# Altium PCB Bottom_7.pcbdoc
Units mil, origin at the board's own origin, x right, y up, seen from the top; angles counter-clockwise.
Board outline 3200 x 3659.5 mil, 4 copper layers (Top Layer, Inner1, Inner2, Bottom Layer), stack 97.3 mil thick; 94 components, 190 nets, 554 pads, 104 vias.
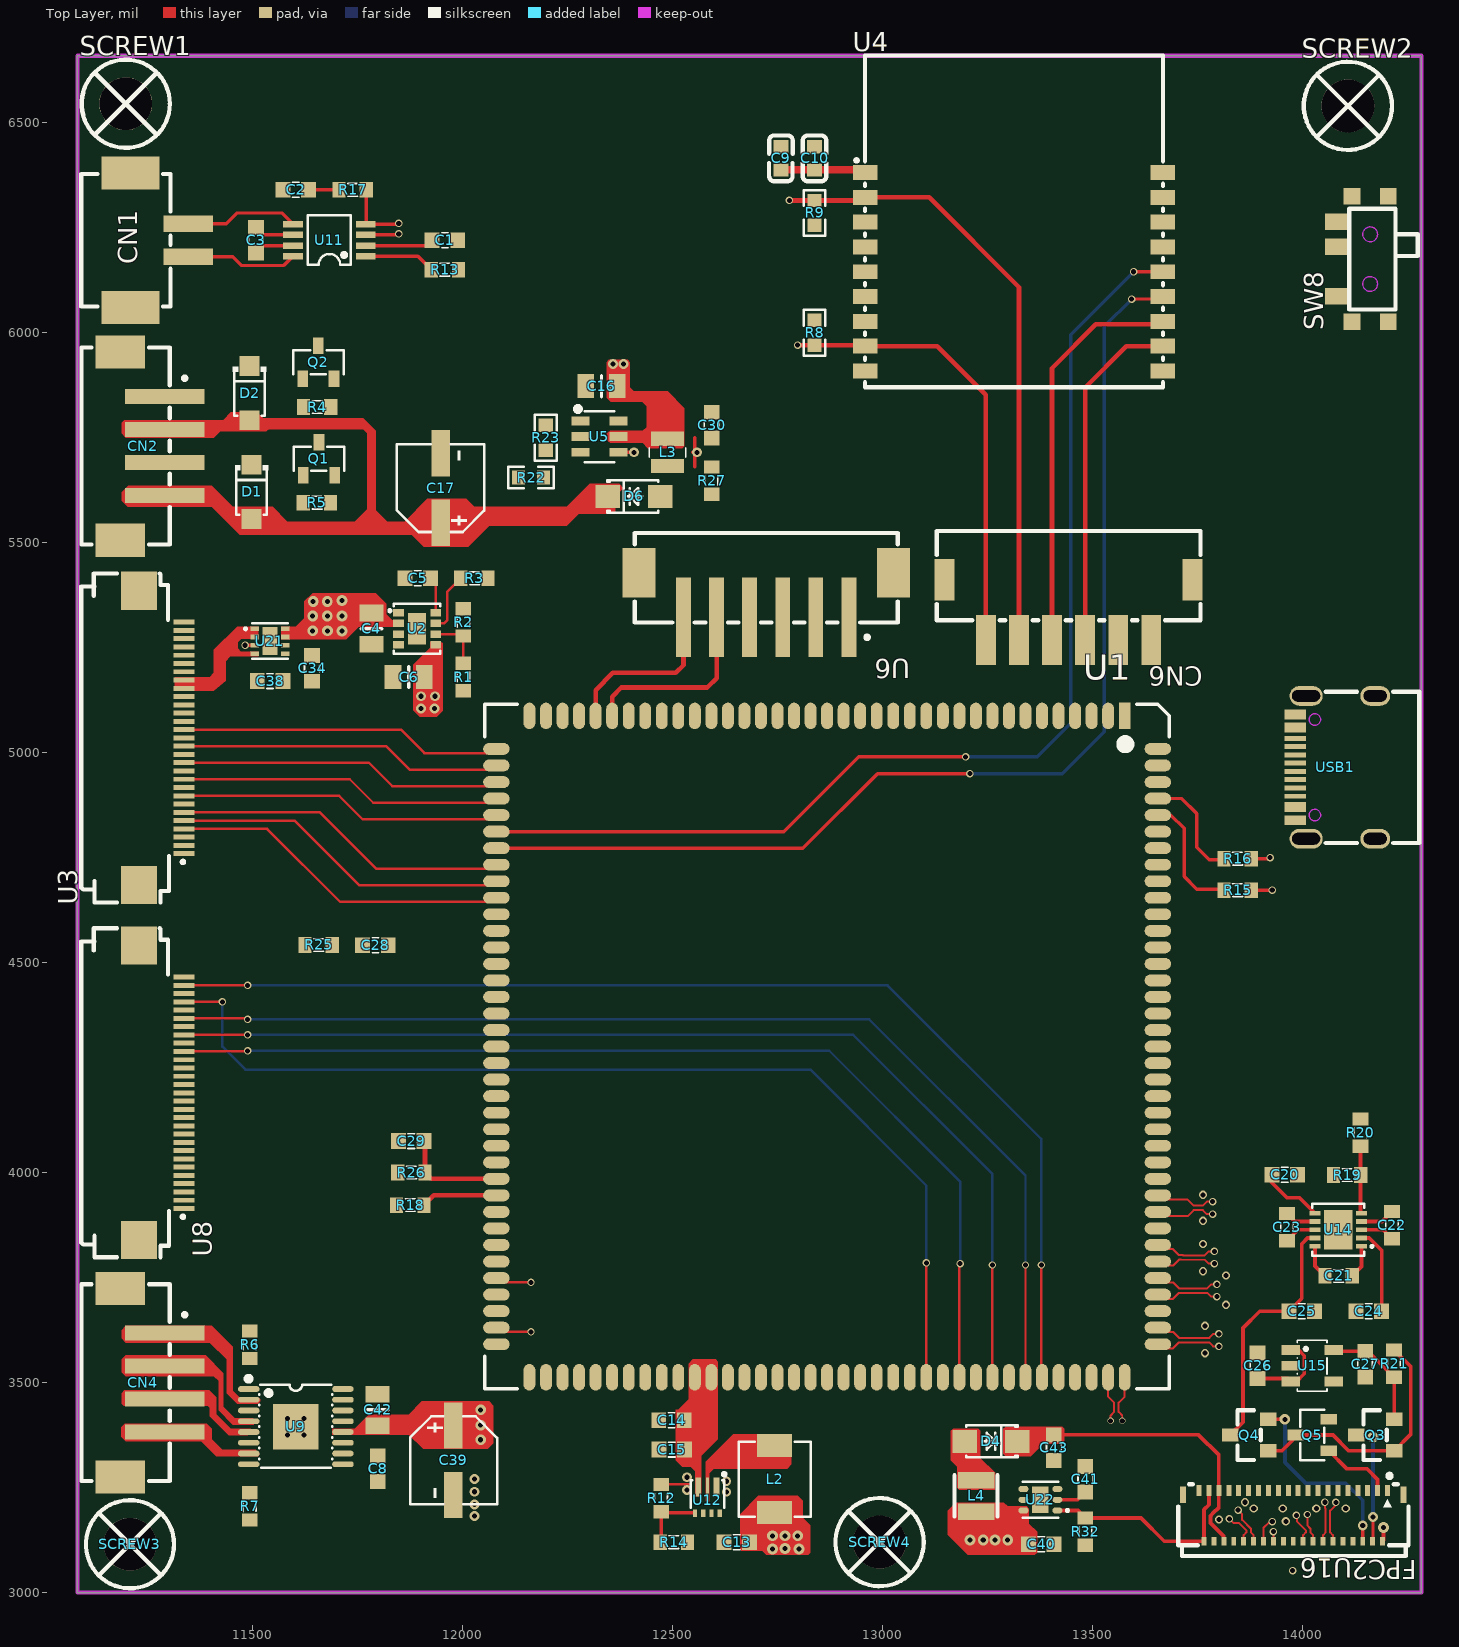
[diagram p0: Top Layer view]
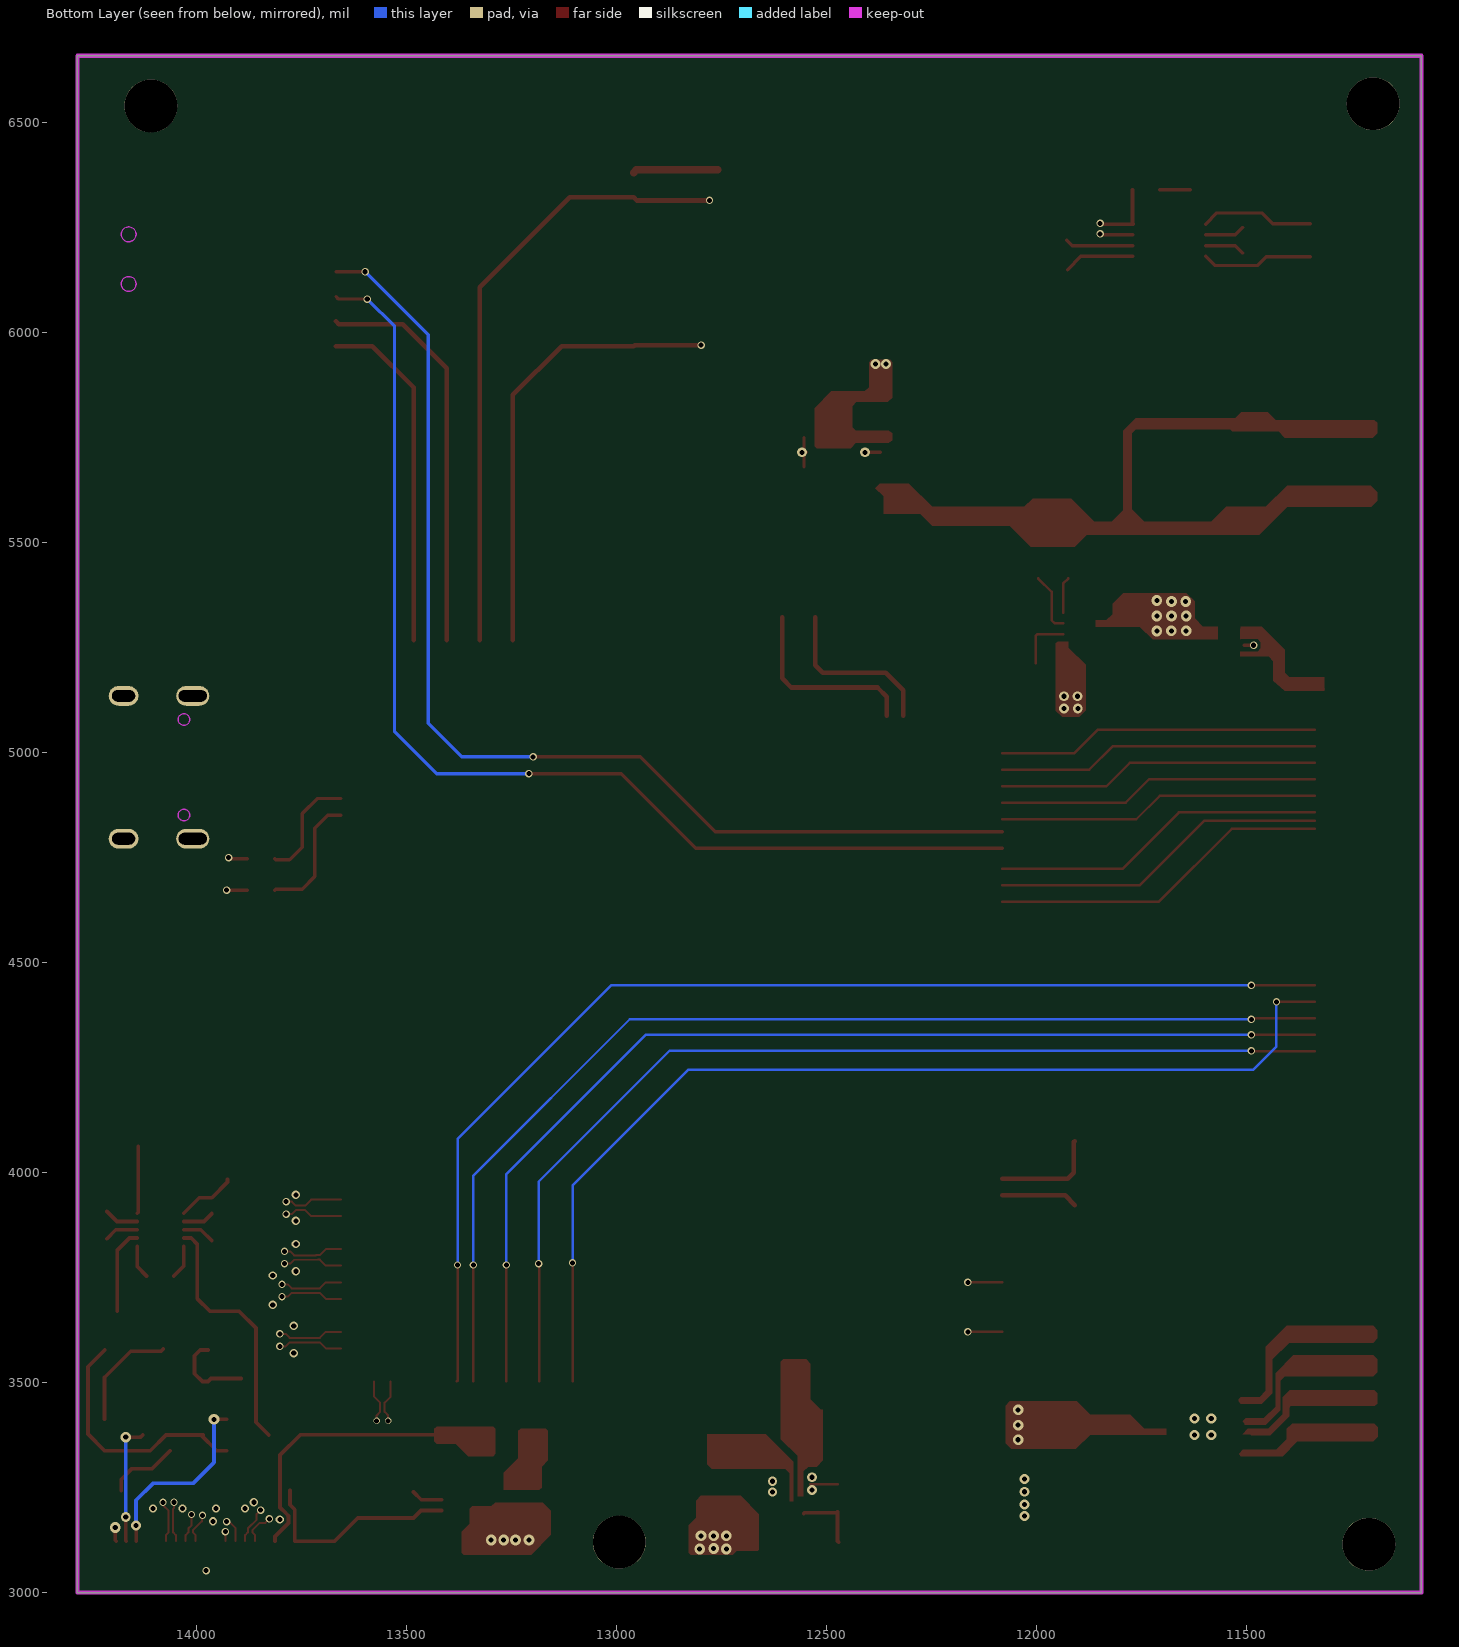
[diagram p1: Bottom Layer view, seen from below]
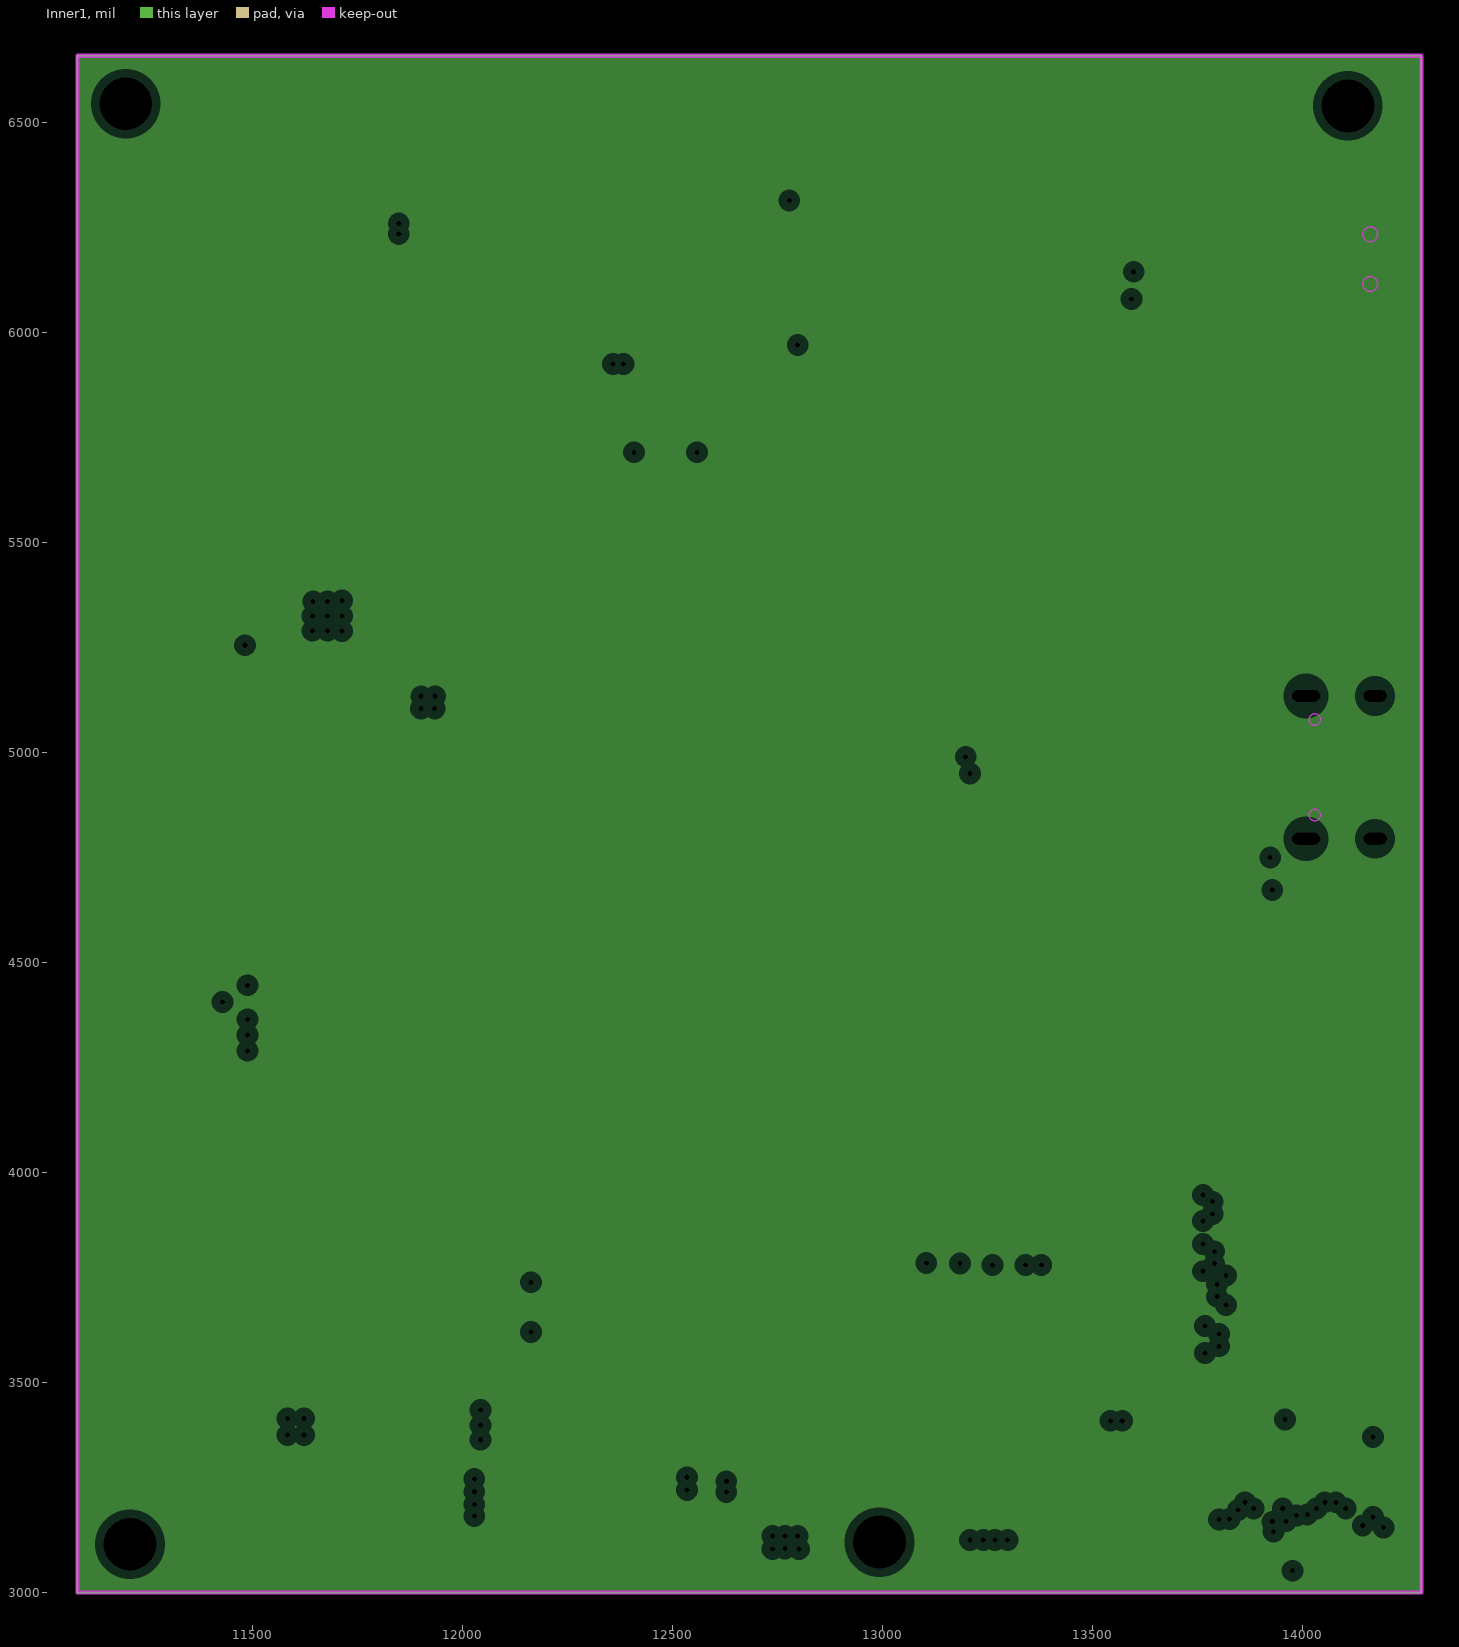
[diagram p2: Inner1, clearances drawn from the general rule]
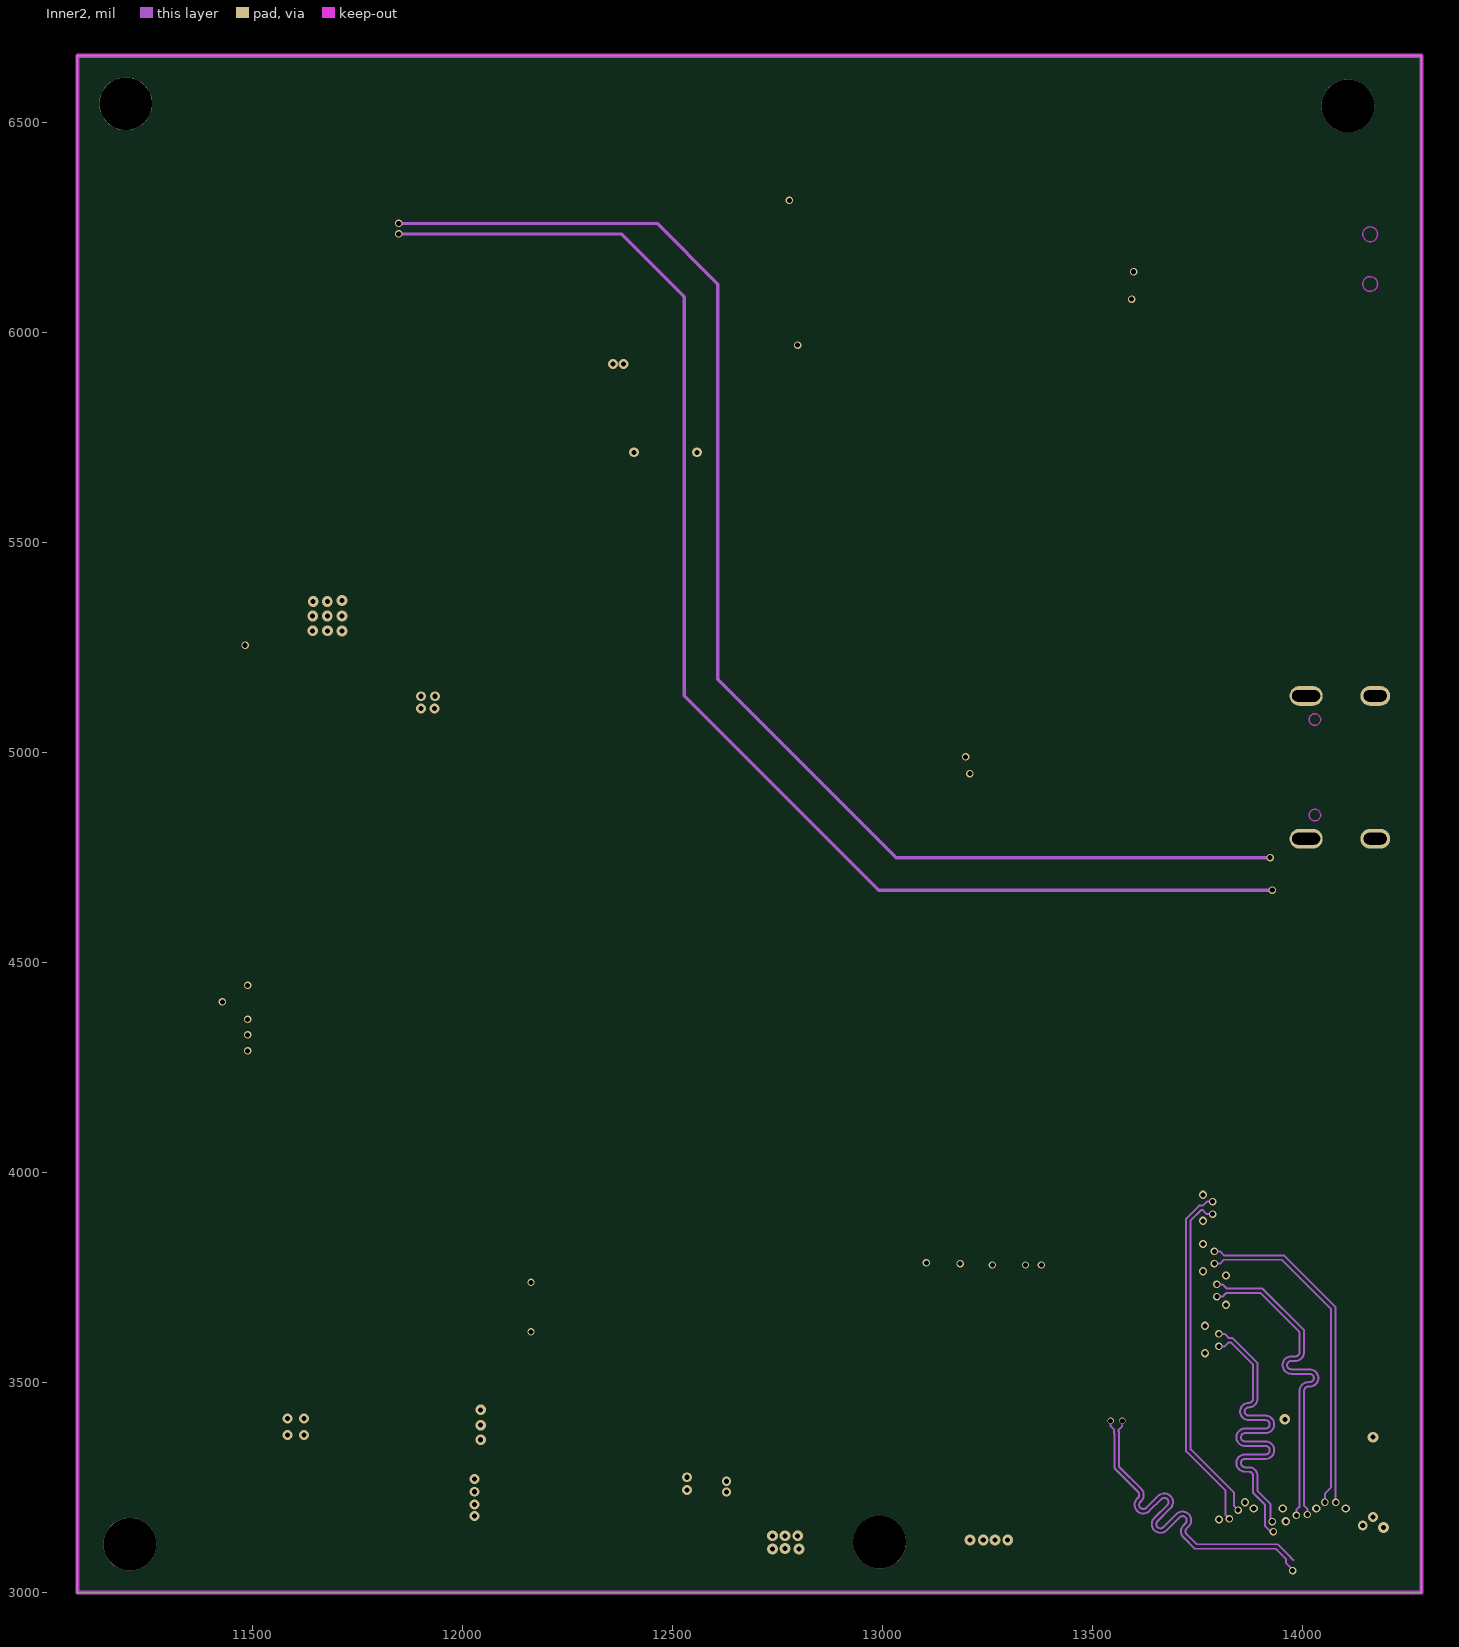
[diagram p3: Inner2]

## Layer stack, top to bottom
Top Solder Mask Layer: solder mask 0.4, Dk 3.3
Top Layer: signal copper 1.4
Inner1: plane copper (thickness not stored)
Inner2: signal copper (thickness not stored)
Dielectric5: surface 18.9, FR4, Dk 4.5
Dielectric6: surface 18.9, PP, Dk 4.5
Dielectric7: surface 18.9, PP, Dk 4.5
Dielectric8: surface 18.9, FR4, Dk 4.5
Dielectric9: surface 18.9, PP, Dk 4.5
Bottom Layer: signal copper 1.4
Bottom Solder Mask Layer: solder mask 0.4, Dk 3.3

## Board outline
11083,6659.5 14283,6659.5 14283,3000 11083,3000

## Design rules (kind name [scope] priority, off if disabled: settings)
BoardOutlineClearance copperThickness1oz [All] p0: genericclearance=10 ignorepadtopadclearanceinfootprint=FALSE except(0: Arc-SplitContinuation Track-SplitContinuation SMDPad-SplitContinuation THPad-SplitContinuation Via-SplitContinuation Fill-SplitContinuation Poly-SplitContinuation Region-SplitContinuation Text-SplitContinuation)
BoardOutlineClearance copperThickness2oz [All] p0: genericclearance=10 ignorepadtopadclearanceinfootprint=FALSE except(0: Arc-SplitContinuation Track-SplitContinuation SMDPad-SplitContinuation THPad-SplitContinuation Via-SplitContinuation Fill-SplitContinuation Poly-SplitContinuation Region-SplitContinuation Text-SplitContinuation)
BoardOutlineClearance copperThicknessInner0.5oz [All] p0: genericclearance=10 ignorepadtopadclearanceinfootprint=FALSE except(0: Arc-SplitContinuation Track-SplitContinuation SMDPad-SplitContinuation THPad-SplitContinuation Via-SplitContinuation Fill-SplitContinuation Poly-SplitContinuation Region-SplitContinuation Text-SplitContinuation)
BoardOutlineClearance 100ohm [All] p0: genericclearance=10 ignorepadtopadclearanceinfootprint=FALSE except(0: Arc-SplitContinuation Track-SplitContinuation SMDPad-SplitContinuation THPad-SplitContinuation Via-SplitContinuation Fill-SplitContinuation Poly-SplitContinuation Region-SplitContinuation Text-SplitContinuation)
BoardOutlineClearance otherClearance [All] p0: genericclearance=10 ignorepadtopadclearanceinfootprint=FALSE except(0: Arc-SplitContinuation Track-SplitContinuation SMDPad-SplitContinuation THPad-SplitContinuation Via-SplitContinuation Fill-SplitContinuation Poly-SplitContinuation Region-SplitContinuation Text-SplitContinuation)
Clearance copperThickness1oz [All] p1: gap=7 ignorepadtopadclearanceinfootprint=FALSE
Clearance copperThickness2oz [All] p1: gap=7 ignorepadtopadclearanceinfootprint=FALSE
Clearance copperThicknessInner0.5oz [All] p1: gap=7 ignorepadtopadclearanceinfootprint=FALSE
Clearance 100ohm [(InNet('DSI-D2P') OR InNet('DSI-D2N') OR InNet('DSI-D1P') OR InNet('DSI-D1N') OR InNet('DSI-CKP') OR InNet('DSI-CKN') OR InNet('DSI-D0P') OR InNet('DSI-D0N') OR InNet('DSI-D3P') OR InNet('DSI-D3N'))] p1: gap=7 ignorepadtopadclearanceinfootprint=FALSE
Clearance otherClearance [All] p1: gap=7 ignorepadtopadclearanceinfootprint=FALSE
DiffPairsRouting differentialPair [All] p1: maxuncoupledlength=10 minlimit=5.9843 maxlimit=Infinity mostfreqgap=5.9843 toplayer_minwidth=4 toplayer_prefwidth=10 toplayer_maxwidth=100 bottomlayer_minwidth=4 bottomlayer_prefwidth=10 bottomlayer_maxwidth=100 midlayer1_minwidth=4 midlayer1_prefwidth=10 midlayer1_maxwidth=100
PasteMaskExpansion pasteMaskExpansion [All] p1: expansion=0
PlaneConnect innerPlane [All] p1: planeconnectstyle=Relief reliefexpansion=20 reliefentries=4 reliefconductorwidth=10 reliefairgap=10
PolygonConnect copperRegion [All] p1: connectstyle=Relief reliefentries=4 reliefconductorwidth=10 polygonreliefangle="90 Angle" airgapwidth=10
RoutingVias viaSize [All] p1: viastyle="Through Hole" holewidth=12.0078 minholewidth=7.874 maxholewidth=248.0316 width=12.0078 minwidth=7.874 maxwidth=248.0316
SolderMaskExpansion solderMaskExpansion [IsVia] p1: useseparateexpansions=TRUE expansion=-1000 expansionbottom=-1000
SolderMaskExpansion solderMaskExpansion [All] p2: useseparateexpansions=TRUE expansion=2.0079 expansionbottom=2.0079
Width copperThickness1oz [All] p1: maxlimit=100 minlimit=4 preferedwidth=4
Width copperThickness2oz [All] p1: maxlimit=100 minlimit=8 preferedwidth=10
Width copperThickness0.5oz [All] p1: maxlimit=100 minlimit=4 preferedwidth=10
Width 100ohm [All] p1: maxlimit=100 minlimit=4 preferedwidth=5

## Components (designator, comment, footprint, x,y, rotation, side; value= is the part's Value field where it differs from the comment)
C1 "100nF" C0603#1 11958,6220 r0 top
C2 "100nF" C0603#1 11603,6340 r180 top
C3 "100nF" C0603#1 11508,6220 r90 top
C4 "100nF" C0603#2 11783,5295 r270 top
C5 "100nF" C0603#1 11893,5415 r0 top
C6 "100nF" C0603#2 11871.7,5180 r0 top
C8 "100nF" C0603#1 11798,3295 r90 top
C9 "100nF" C0603#3 12758,6415 r270 top
C10 "100nF" C0603#3 12838,6415 r270 top
C13 "100nF" C0603#1 12653,3120 r180 top
C14 "100nF" C0603#1 12497.5,3410 r180 top
C15 "100nF" C0603#1 12498,3340.5 r180 top
C16 "100nF" C0603#2 12330.6,5872.6 r0 top
C17 "100uF" CAP-SMD_BD5.0-L5.3-W5.3-LS6.0-FD-H5.7 11948,5630 r90 top
C20 "10uf" 0603_CAP#1 13958,3995 r180 top
C21 "2.2uf" 0603_CAP#2 14086,3754 r0 top
C22 "2.2uf" 0603_CAP#2 14213,3875 r90 top
C23 "2.2uf" 0603_CAP#2 13963,3870 r90 top
C24 "10uf" 0603_CAP#1 14158,3670 r0 top
C25 "10uf" 0603_CAP#1 13998,3670 r180 top
C26 "100nF" C0603#1 13893,3540 r270 top
C27 "100nF" C0603#1 14149.1,3543.9 r90 top
C28 "100nF" C0603#1 11792.6,4541.2 r180 top
C29 "100nF" C0603#1 11878,4075 r0 top
C30 "100nF" C0603#1 12593,5780 r270 top
C34 "100nF" C0603#4 11641.5,5200.3 r90 top
C38 "100nF" C0603#1 11541.5,5170.3 r180 top
C39 "100uF" CAP-SMD_BD5.0-L5.3-W5.3-LS6.0-FD-H5.7 11978,3315 r270 top
C40 "100nF" C0603#1 13378,3115 r180 top
C41 "100nF" C0603#1 13483,3270 r270 top
C42 "22uF" C0805 11798,3435 r270 top
C43 "100nF" C0603#1 13408,3345 r90 top
CN1 "PH2.0-2P-LT" CONN-SMD_PH2.0-1X2PW 11278,6220 r90 top
CN2 "2016WVS-04P" CONN-SMD_2016WVS-04P 11238,5730 r270 top
CN4 "2016WVS-04P" CONN-SMD_2016WVS-04P 11238,3500 r270 top
CN6 "XDWF-0221-06P" CONN-SMD_XDWF-0221-06P 13443,5340 r180 top
D1 "1N4007W" SOD-123FL_L2.7-W1.8-LS3.8-RD 11497.7,5620.9 r270 top
D2 "1N4007W" SOD-123FL_L2.7-W1.8-LS3.8-RD 11492.7,5855.9 r270 top
D4 "DSS16" SOD-123FL_L2.8-W1.8-LS3.7-R-RD 13258,3360 r180 top
D6 "DSS16" SOD-123FL_L2.8-W1.8-LS3.7-R-RD 12408,5610 r0 top
L2 "1uH" IND-SMD_L4.4-W4.2 12743,3270 r90 top
L3 "10uH" IND-SMD_L2.5-W2.0-VLS252012CX-150M 12488,5714.6 r270 top
L4 "10uH" IND-SMD_L2.5-W2.0_FHD252012S-6R8MT 13223,3230 r90 top
Q1 "AO3400A" SOT-23-3_L2.9-W1.3-P1.90-LS2.4-BR#1 11658,5700 r270 top
Q2 "AO3400A" SOT-23-3_L2.9-W1.3-P1.90-LS2.4-BR#2 11656.6,5929.5 r270 top
Q3 "AO3401A" SOT-23_L2.9-W1.3-P1.90-LS2.4-BR 14173,3375 r0 top
Q4 "AO3401A" SOT-23_L2.9-W1.3-P1.90-LS2.4-BR 13873,3375 r0 top
Q5 "AO3400A" SOT-23-3_L2.9-W1.3-P1.90-LS2.4-BR#1 14023,3375 r0 top
R1 "10K" R0603#1 12001.7,5180 r270 top
R2 "10K" R0603#1 12001.7,5310 r270 top
R3 "10K" R0603#1 12028,5415 r180 top
R4 "10K" R0603#2 11653.7,5822.8 r180 top
R5 "10K" R0603#1 11653,5595 r180 top
R6 "10K" R0603#1 11493,3590 r90 top
R7 "10K" R0603#1 11493,3205 r90 top
R8 "10K" R0603#3 12838,6000 r90 top
R9 "10K" R0603#3 12838,6285 r270 top
R12 "10K" R0603#1 12473,3225 r270 top
R13 "10K" R0603#1 11958,6150 r0 top
R14 "10K" R0603#1 12503,3120 r0 top
R15 "10K" R0603#1 13845.5,4672.5 r0 top
R16 "10K" R0603#1 13845.5,4747.5 r0 top
R17 "10K" R0603#1 11738,6340 r180 top
R18 "10K" R0603#1 11875.5,3922.5 r180 top
R19 "100K" 0603_RES 14106,3994 r180 top
R20 "10K" 0603_RES 14138,4095 r90 top
R21 "10K" R0603#1 14218,3545 r270 top
R22 "10K" R0603#3 12163,5655 r180 top
R23 "10K" R0603#3 12198,5750 r270 top
R25 "10K" R0603#1 11657.2,4541.9 r180 top
R26 "10K" R0603#1 11878,4000 r180 top
R27 "10K" R0603#1 12593,5647.8 r270 top
R32 "10K" R0603#1 13483,3145 r90 top
SCREW1 "" M3螺丝 11198,6545 r0 top
SCREW2 "" M3螺丝 14108,6540 r0 top
SCREW3 "" M3螺丝 11208,3115 r0 top
SCREW4 "" M3螺丝 12993,3120 r0 top
SW8 "SK-3296S-01-L1" SW-SMD_3P-P1.50_L2.7-W6.6 14143,6175 r90 top
U1 "CORE-T113-I" CORE-40X40-TAP148 12868,4300 r270 top
U2 "TPS82130SILR" USIP-8_L3.0-W2.8-P0.65-TL-EP 11891.7,5295 r0 top
U3 "AFD01-S29FCA-00" FPC-SMD_29P-P0.50_JS_AFD01-S29FCA-00 11283,5035 r90 top
U4 "2.4GHz" WIFI-SMD_L20.0-W18.0_ESP32-C3-WROOM-02U-N4 13313,6145 r0 top
U5 "MT3608" SOT-23-6_L2.9-W1.6-P0.95-LS2.8-BL 12325.8,5752.5 r270 top
U6 "2016WVS-06P" CONN-SMD_2016WVS-06P 12723,5375 r180 top
U8 "AFD01-S29FCA-00" FPC-SMD_29P-P0.50_JS_AFD01-S29FCA-00 11283,4190 r90 top
U9 "DRV8833PWPR" TSSOP-16_L5.0-W4.4-P0.65-LS6.4-BL-EP 11603,3395 r270 top
U11 "LM4890SS" MSOP-8_L3.0-W3.0-P0.65-LS4.9-BL-1 11683,6220 r90 top
U12 "TPS61022RWUT" VQFN-7_L2.0-W2.0-P0.55-TL_RWU 12583,3220 r270 top
U14 "LP3102QVF" TDFN-10_L3.0-W3.0-P0.50-BL-EP 14085.1,3863.8 r90 top
U15 "ME6211C18M5G-N" SOT-23-5_L3.0-W1.7-P0.95-LS2.8-BR 14023,3540 r180 top
U16 "FPC-0.3HF-39PWBH10" CONN-SMD_FPC-0.3HF-39PWBH10 13973,3180 r180 top locked
U21 "TPS22965DSGR" UDFN-8_L2.0-W2.0-P0.50-TL-EP 11541.5,5265.3 r0 top
U22 "TPS61165DRVR" WSON-6_L2.0-W2.0-P0.65-TL-EP 13376,3220.9 r180 top
USB1 "KH-TYPE-C-16P" USB-C-SMD_KH-TYPE-C-16P 14078,4965 r90 top

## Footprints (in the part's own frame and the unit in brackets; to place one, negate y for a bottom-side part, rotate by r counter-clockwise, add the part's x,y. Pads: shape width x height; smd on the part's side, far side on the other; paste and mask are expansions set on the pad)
0603_CAP#1 [mil]
  rect 35.4x37.4 smd: 1(-30.5,0) 2(30.5,0)
  silkscreen extent -8,-18 8,18
0603_CAP#2 [mil]
  rect 31.5x37.4 smd: 1(-32.5,0) 2(32.5,0)
  silkscreen extent -12,-15 12,15
0603_RES [mil]
  rect 31.5x37.4 smd: 1(-32.5,0) 2(32.5,0)
  silkscreen extent -12,-15 12,15
C0603#1 [mil]
  rect 35.4x37.4 smd: 1(-30.5,0) 2(30.5,0)
  silkscreen extent -8,-18 8,18
C0603#2 [mil]
  rect 39.4x57.1 smd: 1(-37.4,0) 2(37.4,0)
  silkscreen extent 0,-25 0,25
C0603#3 [mil]
  rect 31.5x35.4 smd: 1(-27.6,0) 2(27.6,0)
  silkscreen extent -55,-28 55,28
C0603#4 [mil]
  rect 35.4x37.4 smd: 1(-30.5,0) 2(30.6,0)
  silkscreen extent -8,-18 8,18
C0805 [mil]
  rect 39.4x57.1 smd: 1(-37.4,0) 2(37.4,0)
  silkscreen extent 0,-25 0,25
CAP-SMD_BD5.0-L5.3-W5.3-LS6.0-FD-H5.7 [mil]
  rect 110.2x43.3 smd: 1(-82.7,0) 2(82.7,0)
  silkscreen extent -105,-103 105,104
CONN-SMD_2016WVS-04P [mil]
  rect 35.4x189 smd: 1(-118.1,53.1) 2(-39.4,53.1) 3(39.4,53.1) 4(118.1,53.1)
  rect 78.7x118.1 smd: 5(224.4,-53.1) 6(-224.4,-53.1)
  silkscreen extent -234,-145 234,104
CONN-SMD_2016WVS-06P [mil]
  rect 35.4x189 smd: 1(-196.9,53.1) 2(-118.1,53.1) 3(-39.4,53.1) 4(39.4,53.1) 5(118.1,53.1) 6(196.9,53.1)
  rect 78.7x118.1 smd: 7(303.1,-53.1) 8(-303.1,-53.1)
  silkscreen extent -313,-148 313,104
CONN-SMD_FPC-0.3HF-39PWBH10 [mil]
  rect 11.8x26.4 smd paste+0 mask+2: 1(-229.4,-63) 3(-205.8,-63) 5(-182.2,-63) 7(-158.6,-63) 9(-134.9,-63) 11(-111.3,-63) 13(-87.7,-63) 15(-64.1,-63) 17(-40.4,-63) 19(-16.8,-63) 21(6.8,-63) 23(30.4,-63) 25(54,-63) 27(77.7,-63) 29(101.3,-63) 31(124.9,-63) 33(148.5,-63) 35(172.2,-63) 37(195.8,-63) 39(219.4,-63)
  rect 11.8x19.7 smd paste+0 mask+2: 2(-217.6,57.7) 4(-194,57.7) 6(-170.4,57.7) 8(-146.7,57.7) 10(-123.1,57.7) 12(-99.5,57.7) 14(-75.9,57.7) 16(-52.3,57.7) 18(-28.6,57.7) 20(-5,57.7) 22(18.6,57.7) 24(42.2,57.7) 26(65.9,57.7) 28(89.5,57.7) 30(113.1,57.7) 32(136.7,57.7) 34(160.3,57.7) 36(184,57.7) 38(207.6,57.7)
  rect 13.8x39.4 smd paste+0 mask+2: 40(257.8,-52.6) 41(-267.8,-52.6)
  silkscreen extent -279,-103 269,93
CONN-SMD_PH2.0-1X2PW [mil]
  rect 39.4x118.1 smd: 1(-39.4,-69.1) 2(39.4,-69.1)
  rect 78.7x137.8 smd: 3(160,69.1) 4(-160,69.1)
  silkscreen extent -158,-27 158,186
CONN-SMD_XDWF-0221-06P [mil]
  rect 47.2x118.1 smd: 1(-196.9,71.9) 2(-118.1,71.9) 3(-39.4,71.9) 4(39.4,71.9) 5(118.1,71.9) 6(196.8,71.9)
  rect 47.2x98.4 smd: 7(295.3,-71.9) 8(-295.3,-71.9)
  silkscreen extent -314,-188 314,25
CORE-40X40-TAP148 [mil]
  rect 63x28.3 smd: 1(-787.4,708.7)
  oval 63x28.3 smd: 2(-787.4,669.3) 3(-787.4,629.9) 4(-787.4,590.6) 5(-787.4,551.2) 6(-787.4,511.8) 7(-787.4,472.4) 8(-787.4,433.1) 9(-787.4,393.7) 10(-787.4,354.3) 11(-787.4,315) 12(-787.4,275.6) 13(-787.4,236.2) 14(-787.4,196.9) 15(-787.4,157.5) 16(-787.4,118.1) 17(-787.4,78.7) 18(-787.4,39.4) 19(-787.4,0) 20(-787.4,-39.4) 21(-787.4,-78.7) 22(-787.4,-118.1) 23(-787.4,-157.5) 24(-787.4,-196.9) 25(-787.4,-236.2) 26(-787.4,-275.6) 27(-787.4,-315) 28(-787.4,-354.3) 29(-787.4,-393.7) 30(-787.4,-433.1) 31(-787.4,-472.4) 32(-787.4,-511.8) 33(-787.4,-551.2) 34(-787.4,-590.6) 35(-787.4,-629.9) 36(-787.4,-669.3) 37(-787.4,-708.7) 75(787.4,-708.7) 76(787.4,-669.3) 77(787.4,-629.9) 78(787.4,-590.6) 79(787.4,-551.2) 80(787.4,-511.8) 81(787.4,-472.4) 82(787.4,-433.1) 83(787.4,-393.7) 84(787.4,-354.3) 85(787.4,-315) 86(787.4,-275.6) 87(787.4,-236.2) 88(787.4,-196.9) 89(787.4,-157.5) 90(787.4,-118.1) 91(787.4,-78.7) 92(787.4,-39.4) 93(787.4,0) 94(787.4,39.4) 95(787.4,78.7) 96(787.4,118.1) 97(787.4,157.5) 98(787.4,196.9) 99(787.4,236.2) 100(787.4,275.6) 101(787.4,315) 102(787.4,354.3) 103(787.4,393.7) 104(787.4,433.1) 105(787.4,472.4) 106(787.4,511.8) 107(787.4,551.2) 108(787.4,590.6) 109(787.4,629.9) 110(787.4,669.3) 111(787.4,708.7)
  oval 28.3x63 smd: 38(-708.7,-787.4) 39(-669.3,-787.4) 40(-629.9,-787.4) 41(-590.6,-787.4) 42(-551.2,-787.4) 43(-511.8,-787.4) 44(-472.4,-787.4) 45(-433.1,-787.4) 46(-393.7,-787.4) 47(-354.3,-787.4) 48(-315,-787.4) 49(-275.6,-787.4) 50(-236.2,-787.4) 51(-196.8,-787.4) 52(-157.5,-787.4) 53(-118.1,-787.4) 54(-78.7,-787.4) 55(-39.4,-787.4) 56(0,-787.4) 57(39.4,-787.4) 58(78.7,-787.4) 59(118.1,-787.4) 60(157.5,-787.4) 61(196.9,-787.4) 62(236.2,-787.4) 63(275.6,-787.4) 64(315,-787.4) 65(354.3,-787.4) 66(393.7,-787.4) 67(433.1,-787.4) 68(472.4,-787.4) 69(511.8,-787.4) 70(551.2,-787.4) 71(590.6,-787.4) 72(629.9,-787.4) 73(669.3,-787.4) 74(708.7,-787.4) 112(708.7,787.4) 113(669.3,787.4) 114(629.9,787.4) 115(590.6,787.4) 116(551.2,787.4) 117(511.8,787.4) 118(472.4,787.4) 119(433.1,787.4) 120(393.7,787.4) 121(354.3,787.4) 122(315,787.4) 123(275.6,787.4) 124(236.2,787.4) 125(196.9,787.4) 126(157.5,787.4) 127(118.1,787.4) 128(78.7,787.4) 129(39.4,787.4) 130(0,787.4) 131(-39.4,787.4) 132(-78.7,787.4) 133(-118.1,787.4) 134(-157.5,787.4) 135(-196.8,787.4) 136(-236.2,787.4) 137(-275.6,787.4) 138(-315,787.4) 139(-354.3,787.4) 140(-393.7,787.4) 141(-433.1,787.4) 142(-472.4,787.4) 143(-511.8,787.4) 144(-551.2,787.4) 145(-590.6,787.4) 146(-629.9,787.4) 147(-669.3,787.4) 148(-708.7,787.4)
  silkscreen extent -815,-815 815,815
FPC-SMD_29P-P0.50_JS_AFD01-S29FCA-00 [mil]
  rect 11.8x49.2 smd paste+0 mask+2: 1(-275.6,-53.6) 2(-255.9,-53.6) 3(-236.2,-53.6) 4(-216.5,-53.6) 5(-196.8,-53.6) 6(-177.2,-53.6) 7(-157.5,-53.6) 8(-137.8,-53.6) 9(-118.1,-53.6) 10(-98.4,-53.6) 11(-78.7,-53.6) 12(-59.1,-53.6) 13(-39.4,-53.6) 14(-19.7,-53.6) 15(0,-53.6) 16(19.7,-53.6) 17(39.4,-53.6) 18(59,-53.6) 19(78.7,-53.6) 20(98.4,-53.6) 21(118.1,-53.6) 22(137.8,-53.6) 23(157.5,-53.6) 24(177.2,-53.6) 25(196.8,-53.6) 26(216.5,-53.6) 27(236.2,-53.6) 28(255.9,-53.6) 29(275.6,-53.6)
  rect 90.6x86.6 smd paste+0 mask+2: 30(350.4,53.6) 31(-350.4,53.6)
  silkscreen extent -392,-55 392,191
IND-SMD_L2.5-W2.0-VLS252012CX-150M [mil]
  rect 33.5x78.7 smd: 1(-32.7,0) 2(32.6,0)
  silkscreen extent -11,-43 11,43
IND-SMD_L2.5-W2.0_FHD252012S-6R8MT [mil]
  rect 39.4x86.6 smd: 1(-37.4,0) 2(37.4,0)
  silkscreen extent -49,-51 49,52
IND-SMD_L4.4-W4.2 [mil]
  rect 55.1x83.5 smd: 1(79.8,0) 2(-79.8,0)
  silkscreen extent -90,-86 90,86
M3螺丝 [mil]
  round 126 hole 126 paste+0 mask+4: 1(0,0)
  silkscreen extent -105,-105 105,105
MSOP-8_L3.0-W3.0-P0.65-LS4.9-BL-1 [mil]
  rect 16x47.2 smd: 1(-38.4,-86.6) 2(-12.8,-86.6) 3(12.8,-86.6) 4(38.4,-86.6) 5(38.4,86.6) 6(12.8,86.6) 7(-12.8,86.6) 8(-38.4,86.6)
  silkscreen extent -58,-51 59,51
R0603#1 [mil]
  rect 31.5x37.4 smd: 1(-32.5,0) 2(32.5,0)
  silkscreen extent -12,-15 12,15
R0603#2 [mil]
  rect 31.5x37.4 smd: 1(-32.5,0) 2(32.4,0)
  silkscreen extent -12,-15 12,15
R0603#3 [mil]
  rect 31.8x34 smd paste-3937 mask+2: 1(-29.7,0) 2(29.7,0)
  silkscreen extent -54,-26 54,26
SOD-123FL_L2.7-W1.8-LS3.8-RD [mil]
  rect 47.2x47.2 smd: 1(-64.4,0) 2(64.4,0)
  silkscreen extent -63,-40 54,39
SOD-123FL_L2.8-W1.8-LS3.7-R-RD [mil]
  rect 58.3x55.1 smd paste+0 mask+2: 1(62.6,0) 2(-62.6,0)
  silkscreen extent -64,-38 58,38
SOT-23-3_L2.9-W1.3-P1.90-LS2.4-BR#1 [mil]
  rect 39.4x25.6 smd: 1(39.4,-37.4) 2(39.4,37.4) 3(-39.4,0)
  silkscreen extent -29,-60 29,60
SOT-23-3_L2.9-W1.3-P1.90-LS2.4-BR#2 [mil]
  rect 39.4x25.6 smd: 1(39.4,-37.4) 2(39.4,37.4) 3(-39.3,0)
  silkscreen extent -29,-60 29,60
SOT-23-5_L3.0-W1.7-P0.95-LS2.8-BR [mil]
  rect 43.3x23.6 smd: 1(51.2,-37.4) 2(51.2,0) 3(51.2,37.4) 4(-51.2,37.4) 5(-51.2,-37.4)
  silkscreen extent -35,-61 35,61
SOT-23-6_L2.9-W1.6-P0.95-LS2.8-BL [mil]
  rect 20.9x42.2 smd: 1(-37.4,-45.2) 2(0,-45.2) 3(37.4,-45.2) 4(37.4,45.3) 5(0,45.3) 6(-37.4,45.3)
  silkscreen extent -72,-57 61,35
SOT-23_L2.9-W1.3-P1.90-LS2.4-BR [mil]
  rect 39.4x31.5 smd: 1(45.3,-37.4) 2(45.3,37.4) 3(-45.3,0)
  silkscreen extent -28,-59 28,59
SW-SMD_3P-P1.50_L2.7-W6.6 [mil]
  rect 39.4x39.4 smd: 0(-149.6,-61.4) 0(-149.6,25.2) 0(149.6,-61.4) 0(149.6,25.2)
  rect 39.4x55.1 smd: 1(-88.6,61.4) 2(29.5,61.4) 3(88.6,61.4)
  Board Outline Layer circle w0.1: c-59.1,-18.1 r17.7
  Board Outline Layer circle w0.1: c59.1,-18.1 r17.7
  Board Outline Layer region: -59.1,-35.8 -66.78,-34.05 -72.94,-29.14 -76.36,-22.04 -76.36,-14.16 -72.94,-7.06 -66.78,-2.15 -59.1,-0.4 -59.1,-0.4 -51.42,-2.15 -45.26,-7.06 -41.84,-14.16 -41.84,-22.04 -45.26,-29.14 -51.42,-34.05 -59.1,-35.8
  Board Outline Layer region: -59.1,-35.8 -66.78,-34.05 -72.94,-29.14 -76.36,-22.04 -76.36,-14.16 -72.94,-7.06 -66.78,-2.15 -59.1,-0.4 -59.1,-0.4 -51.42,-2.15 -45.26,-7.06 -41.84,-14.16 -41.84,-22.04 -45.26,-29.14 -51.42,-34.05 -59.1,-35.8
  Board Outline Layer region: 59.1,-35.8 51.42,-34.05 45.26,-29.14 41.84,-22.04 41.84,-14.16 45.26,-7.06 51.42,-2.15 59.1,-0.4 59.1,-0.4 66.78,-2.15 72.94,-7.06 76.36,-14.16 76.36,-22.04 72.94,-29.14 66.78,-34.05 59.1,-35.8
  Board Outline Layer region: 59.1,-35.8 51.42,-34.05 45.26,-29.14 41.84,-22.04 41.84,-14.16 45.26,-7.06 51.42,-2.15 59.1,-0.4 59.1,-0.4 66.78,-2.15 72.94,-7.06 76.36,-14.16 76.36,-22.04 72.94,-29.14 66.78,-34.05 59.1,-35.8
  silkscreen extent -120,-131 120,32
TDFN-10_L3.0-W3.0-P0.50-BL-EP [mil]
  rect 11x26.2 smd: 1(-39.4,-55.4) 2(-19.7,-55.4) 3(0,-55.4) 4(19.7,-55.4) 5(39.4,-55.4) 6(39.4,55.4) 7(19.7,55.4) 8(0,55.4) 9(-19.7,55.4) 10(-39.4,55.4)
  rect 94.5x66.9 smd: 11(0,0)
  silkscreen extent -62,-83 62,62
TSSOP-16_L5.0-W4.4-P0.65-LS6.4-BL-EP [mil]
  oval 13.8x51.2 smd: 1(-89.6,-112.2) 2(-64,-112.2) 3(-38.4,-112.2) 4(-12.8,-112.2) 5(12.8,-112.2) 6(38.4,-112.2) 7(64,-112.2) 8(89.6,-112.2) 9(89.6,112.2) 10(64,112.2) 11(38.4,112.2) 12(12.8,112.2) 13(-12.8,112.2) 14(-38.4,112.2) 15(-64,112.2) 16(-89.6,112.2)
  rect 107.9x107.9 smd: 17(0,0)
  silkscreen extent -120,-118 98,87
UDFN-8_L2.0-W2.0-P0.50-TL-EP [mil]
  rect 19.9x11 smd: 1(-36.6,29.6) 2(-36.6,9.9) 3(-36.6,-9.8) 4(-36.6,-29.5) 5(36.5,-29.5) 6(36.5,-9.8) 7(36.5,9.9) 8(36.5,29.6)
  rect 35.4x66.9 smd: 9(0,0)
  silkscreen extent -61,-42 42,42
USB-C-SMD_KH-TYPE-C-16P [mil]
  oval 47.2x78.7 hole 27.6 slot 66.9 at 90 deg paste+0 mask+2: 1(-170.1,69.5) 2(170.1,69.5)
  oval 47.2x70.9 hole 27.6 slot 55.1 at 90 deg paste+0 mask+2: 3(-170.1,-95.1) 4(170.1,-95.1)
  rect 11.8x51.2 smd paste-3937 mask+2: A1(-131.9,95.1) A4(-100.4,95.1) A5(-49.2,95.1) A6(-9.8,95.1) A7(9.8,95.1) A8(49.2,95.1) A9(100.4,95.1) A12(131.9,95.1) B1(120.1,95.1) B4(88.6,95.1) B5(68.9,95.1) B6(29.5,95.1) B7(-29.5,95.1) B8(-68.9,95.1) B9(-88.6,95.1) B12(-120.1,95.1)
  Board Outline Layer circle w0.1: c-113.8,48.6 r13.8
  Board Outline Layer circle w0.1: c113.8,48.6 r13.8
  Board Outline Layer region: -113.8,34.8 -119.79,36.17 -124.59,40 -127.25,45.53 -127.25,51.67 -124.59,57.2 -119.79,61.03 -113.8,62.4 -113.8,62.4 -107.81,61.03 -103.01,57.2 -100.35,51.67 -100.35,45.53 -103.01,40 -107.81,36.17 -113.8,34.8
  Board Outline Layer region: -113.8,34.8 -119.79,36.17 -124.59,40 -127.25,45.53 -127.25,51.67 -124.59,57.2 -119.79,61.03 -113.8,62.4 -113.8,62.4 -107.81,61.03 -103.01,57.2 -100.35,51.67 -100.35,45.53 -103.01,40 -107.81,36.17 -113.8,34.8
  Board Outline Layer region: 113.8,34.8 107.81,36.17 103.01,40 100.35,45.53 100.35,51.67 103.01,57.2 107.81,61.03 113.8,62.4 113.8,62.4 119.79,61.03 124.59,57.2 127.25,51.67 127.25,45.53 124.59,40 119.79,36.17 113.8,34.8
  Board Outline Layer region: 113.8,34.8 107.81,36.17 103.01,40 100.35,45.53 100.35,51.67 103.01,57.2 107.81,61.03 113.8,62.4 113.8,62.4 119.79,61.03 124.59,57.2 127.25,51.67 127.25,45.53 124.59,40 119.79,36.17 113.8,34.8
  silkscreen extent -180,-200 180,23
USIP-8_L3.0-W2.8-P0.65-TL-EP [mil]
  rect 25.6x17.7 smd: 1(-44.3,38.4) 2(-44.3,12.8) 3(-44.3,-12.8) 4(-44.3,-38.4) 5(44.3,-38.4) 6(44.3,-12.8) 7(44.3,12.8) 8(44.3,38.4)
  rect 43.3x74.8 smd: 9(0,0)
  silkscreen extent -68,-59 55,59
VQFN-7_L2.0-W2.0-P0.55-TL_RWU [mil]
  rect 45.3x13.8 smd paste+0 mask+2: 1(-31.5,21.6) 3(-31.5,-21.7)
  rect 57.1x7.9 smd paste+0 mask+2: 2(-25.6,0)
  rect 17.7x9.8 smd paste+0 mask+2: 4(31.5,-29.5) 5(31.5,-9.8) 6(31.5,9.8) 7(31.5,29.5)
  silkscreen extent -66,-40 18,44
WIFI-SMD_L20.0-W18.0_ESP32-C3-WROOM-02U-N4 [mil]
  rect 59.1x35.4 smd paste+0 mask+2: 1(-354.3,236.2) 2(-354.3,177.2) 3(-354.3,118.1) 4(-354.3,59.1) 5(-354.3,0) 6(-354.3,-59.1) 7(-354.3,-118.1) 8(-354.3,-177.2) 9(-354.3,-236.2) 10(354.3,-236.2) 11(354.3,-177.2) 12(354.3,-118.1) 13(354.3,-59.1) 14(354.3,0) 15(354.3,59.1) 16(354.3,118.1) 17(354.3,177.2) 18(354.3,236.2)
  silkscreen extent -379,-275 355,515
WSON-6_L2.0-W2.0-P0.65-TL-EP [mil]
  oval 23.9x14.3 smd: 1(-40.4,25.6) 2(-40.4,0) 3(-40.4,-25.6) 4(40.5,-25.6) 5(40.5,0) 6(40.5,25.6)
  rect 39.4x63 smd: 7(0,0)
  silkscreen extent -67,-42 42,42

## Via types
v1: diameter 17.7, hole 12, Top Layer to Bottom Layer, 40 vias
v2: diameter 25.6, hole 12, Top Layer to Bottom Layer, 25 vias
v3: diameter 23.6, hole 12, Top Layer to Bottom Layer, 16 vias
v4: diameter 19.7, hole 12, Top Layer to Bottom Layer, 15 vias
v5: diameter 24, hole 12, Top Layer to Bottom Layer, 4 vias
v6: diameter 15.7, hole 12, Top Layer to Bottom Layer, 2 vias
v7: diameter 21.7, hole 12, Top Layer to Bottom Layer, 2 vias

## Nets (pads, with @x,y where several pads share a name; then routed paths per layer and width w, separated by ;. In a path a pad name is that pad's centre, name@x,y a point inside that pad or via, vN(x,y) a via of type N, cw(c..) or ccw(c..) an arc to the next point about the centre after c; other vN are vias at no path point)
1ADC_RDY: U1.38 U3.16 | length 767.2
  Top Layer w5.9: U3.16 11853.3,5054.7 11909.3,4998.7 U1.38@12080.6,4998.7
1SCLK: U1.42 U3.8 | length 767.2
  Top Layer w5.9: U3.8 11705.8,4897.2 11761.8,4841.2 U1.42@12080.6,4841.2
1SPISIMO: U1.40 U3.12 | length 767.2
  Top Layer w5.9: U3.12 11777.1,4975.9 11833.1,4919.9 U1.40@12080.6,4919.9
1SPISOMI: U1.41 U3.10 | length 767.2
  Top Layer w5.9: U3.10 11731.4,4936.6 11787.4,4880.6 U1.41@12080.6,4880.6
1SPISTE: U1.39 U3.14 | length 767.2
  Top Layer w5.9: U3.14 11817.7,5015.3 11873.7,4959.3 U1.39@12080.6,4959.3
3V3: U3.1 U3.2
3V3_AFE: C28.2 R25.1 U2.1
5V: C14.1 C15.1 C39.1 C40.2 C42.2 L4.1 R12.1 U1.85 U1.86 U1.87 U9.12 U12.3 U22.6 | length 65
  Top Layer w5.9: R12.1 12538,3257.5
  other v2: 13208,3125 13239.8,3125 13268,3125 13298,3125 12043,3363.8 12043,3398.4 12043,3435
  other v3: 12534.4,3244.1 12534.4,3274.5
12V: C17.1 CN2.2 CN2.4 D1.2 D2.2 D6.2 R22.2
$25N41: C5.2 U2.8 | length 86.8
  Top Layer w5.9: C5.2 11936,5402.5 U2.8
$25N130: R1.1 R2.2 U2.6 | length 132.6
  Top Layer w5.9: U2.6 11997,5282.2 R2.2 R1.1
$25N148: CN4.1 U9.2
$25N149: CN4.2 U9.4
$25N150: CN4.3 U9.5
$25N151: CN4.4 U9.7
$25N152: CN2.1 D2.1 Q2.3
$25N153: CN2.3 D1.1 Q1.3
$25N161: C8.2 U9.11
$25N181: L2.1 U12.2
$25N184: R12.2 R14.1 U12.4 | length 155.7
  Top Layer w9: R14.1 12473,3122.5 R12.2 12475.5,3190 12552,3190 U12.4
$25N191: Q4.2 U16.6 | length 452.2
  Top Layer w8: U16.6 v3(14143.4,3160)
  Top Layer w9: Q4.2@13928.3,3412.4 v2(13958,3412.4)
  Bottom Layer w9: v2(13958,3412.4) 13958,3310 14008,3260 14103,3260 14143.4,3219.6 v3(14143.4,3160)
$25N194: Q3.1 Q4.1 Q5.3 R21.1 | length 598.9
  Top Layer w9: Q4.1@13928.3,3337.6 13951.2,3337.6 Q5.3@13988.6,3375 ; Q5.3 Q5.3@13988.6,3375 ; R21.1 14258,3537.5 14258,3377.3 Q3.1 14109.7,3337.6 14072.3,3375 Q5.3@13988.6,3375
$25N195: Q3.3 U16.4 | length 290.5
  Top Layer w8: U16.4 14168,3123.4 14168,3145 v3(14168,3180)
  Top Layer w9: Q3.3 14132.7,3370 v2(14168,3370)
  Bottom Layer w9: v3(14168,3180) v2(14168,3370)
$25N207: R19.1 R20.1 U14.5 | length 160.3
  Top Layer w9: R20.1 14138,3905.7 U14.5
$25N212: C23.2 U14.7 | length 74.6
  Top Layer w9: C23.2 13982,3883.5 U14.7
$25N213: C23.1 U14.8 | length 77.6
  Top Layer w9: C23.1 13989.3,3863.8 U14.8
$25N214: C21.2 U14.1 | length 79.5
  Top Layer w9: C21.2 14140.5,3776.1 U14.1
$25N215: C22.2 U14.4 | length 82.4
  Top Layer w9: U14.4 14189,3883.5 C22.2
$25N216: C22.1 U14.3 | length 81.3
  Top Layer w9: U14.3 14191.7,3863.8 C22.1
$25N217: C21.1 U14.10 | length 80.3
  Top Layer w9: U14.10 14029.7,3777.8 C21.1
$25N282: C34.2 U21.6
$25N291: SW8.3 U21.3 | length 22.7
  Top Layer w8: v1(11482.3,5255.6) 11504.9,5255.6 U21.3
$25N348: C41.2 U22.2 | length 74.3
  Top Layer w9: U22.2 13464.4,3220.9 C41.2
$25N352: D4.1 L4.2 U22.4
$25N531: R22.1 R23.2 U5.3
$25N536: CN6.6 R8.1 U4.8 | length 1081
  Top Layer w11: v1(12798,5970.3) R8.1 12956.2,5970.3 U4.8 13130.2,5967.8 13246.2,5851.8 CN6.6
$25N537: C9.2 C10.2 CN6.1 U4.1 | length 203.2
  Top Layer w18: C9.2 C10.2 12952.4,6387.4 U4.1
$25N539: CN6.5 R9.1 U4.2 | length 1478.8
  Top Layer w11: v1(12778,6315) 12778.3,6314.7 R9.1 12951.2,6314.7 U4.2 13110.8,6322.2 13324.9,6108.1 CN6.5
$25N544: CN6.4 U4.12 | length 957.3
  Top Layer w11: CN6.4 13403.6,5915.6 13508,6020 13660.4,6020 U4.12
$25N545: CN6.3 U4.11 | length 827
  Top Layer w11: CN6.3 13482.4,5869.4 13580.8,5967.8 U4.11
$25N598: D6.1 L3.2 U5.1
$28N1: U1.91
$28N2: U1.90
$28N45: U1.54
$28N46: U1.55
$28N47: U1.56
$28N48: U1.57
$28N49: U1.58
$28N72: U1.50
$28N135: U1.146
$28N136: U1.147
$28N153: R16.2 R17.1 U11.4 | length 3458.2
  Top Layer w8: U11.4 11846.4,6258.4 v1(11848,6260) ; R16.2 13920.5,4747.5 v1(13923,4750)
  Top Layer w9: U11.4 11770.5,6259.3 R17.1
  Inner2 w8: v1(11848,6260) 12463,6260 12608,6115 12608,5175 13033,4750 v1(13923,4750)
$28N155: R13.1 U11.1 | length 169
  Top Layer w8: U11.1 11893.9,6181.6 R13.1
$28N157: C1.1 U11.2 | length 163.2
  Top Layer w8: U11.2 11914.7,6207.2 C1.1
$28N159: C2.1 R17.2 | length 72
  Top Layer w9: C2.1 R17.2
$28N163: CN1.2 U11.5 | length 270.9
  Top Layer w8: CN1.2 11437.4,6259.4 11463,6285 11569.8,6285 U11.5
$28N164: CN1.1 U11.8 | length 266.8
  Top Layer w8: CN1.1 11452.4,6180.6 11473,6160 11574.8,6160 U11.8
$28N197: R15.2 U11.3 | length 3413
  Top Layer w8: U11.3 11845.8,6232.8 v1(11848,6235) ; R15.2 v1(13928,4672.5)
  Inner2 w8: v1(11848,6235) 12378,6235 12528,6085 12528,5135 12990.5,4672.5 v1(13928,4672.5)
+VPS: C3.2 C4.1 C13.1 C16.2 L2.2 L3.1 R13.2 R25.2 R27.2 U2.2 U5.5 U8.11 U8.12 U11.6 U12.5 U12.7 U21.7 U21.8 | length 95.7
  Top Layer w8: C3.2 11525.7,6232.8 U11.6
  other v2: 12738,3103.8 12801.3,3103.8 12768,3105 12738,3135 12768,3135 12798,3135 11643,5290 11678.3,5290 11713,5289.8 11643,5325 11678,5325 11713,5325 11644.3,5360 11678,5360 11713,5362.4
  other v3: 12358,5925 12383,5925
A: U1.34
A1: U1.94 U9.16
A2: U1.95 U9.15
A11/TP_X2: U1.21
A17/MIC_DET: U1.6
A18/FEL/3V3: R18.1 U1.65 U6.4 | length 182.2
  Top Layer w11: R18.1 11931.2,3945.7 U1.65
ACS: U1.122
ADRDY: U1.127
AGND: U3.3 U3.7 U3.9 U3.11 U3.13 U3.15 U3.17 U3.20 U3.23 U3.29 U8.13 U8.14 U8.19 U8.21 U8.23 U8.25 U8.27 U8.29
ASCLK: U1.123
ASCO: U1.126
ASDI: U1.125
B: U1.35
B1: U1.97 U9.9
B2: U1.96 U9.10
B9/TVIN0: U1.17
B11/TP_Y1: U1.22
B13/GPADC1: U1.10
B16/LINEINL: U1.3
B17/FMINL: U1.1
BAT_CE: U3.24
BAT_CHG1: U3.26
BAT_PGOOD: U3.25
BATT_SCL: U1.75 U3.27
BATT_SDA: U1.81 U3.28
C2/PF0/SDC0_D1/JTAG_MS/R_JTAG_MS/3V3: U1.53
C9/TVIN1: U1.19
C11/TP_Y2: U1.24
C12/TP_X1: U1.23
C13/GPADC0: U1.11
C16/LINEINR: U1.4
C17/FMINR: U1.2
COL1: U1.132
COL2: U1.131
COL3: U1.130
COL4: U1.128
D3/PF6/SDC0_DET/3V3: U1.52
D7/PG18/UART0_RX/3V3: U1.32 U6.5 | length 457.6
  Top Layer w11: U1.32 12356.2,5133.2 12378,5155 12583,5155 12604.9,5176.9 U6.5
D15/MICIN2N: U1.142
D16/MICIN3N: U1.140
D17/MICIN3P: U1.139
D19/MICIN1P: U1.138
D20/MICIN1N: U1.137
DIAG_END: U1.47 U3.4 | length 816.2
  Top Layer w5.9: U3.4 11534.5,4818.5 11708.7,4644.3 U1.47@12080.6,4644.3
DSI-CKN: U1.111 U16.22 | length 1055.3
  Top Layer w4.7: 13537.3,3502.6 13537.3,3466.4 13551.6,3452.1 13551.6,3430 13543.2,3421.6 13543.2,3409 ; v6(13570.8,3409) 13570.8,3421.6 13562.3,3430 13562.3,3452.1 13576.7,3466.4 U1.111@13576.7,3502.6
  Inner2 w4.7: 13543.2,3409 13543.2,3396.4 13551.6,3388 13551.6,3378.9 13552.3,3378.2 13552.3,3295.6 13608.3,3239.6 ; 13606.3,3223.5 13608.3,3225.5 ; 13606.36,3223.54 ccw(c13621,3208.9) 13635.64,3194.26 ; 13608.27,3225.43 ccw(c13601.2,3232.5) 13608.27,3239.57 ; 13635.6,3194.3 13663.8,3222.5 ; 13647.06,3177.54 ccw(c13661.7,3162.9) 13676.34,3148.26 ; 13647.1,3177.5 13678,3208.3 ; 13663.83,3222.47 cw(c13670.9,3215.4) 13677.97,3208.33 ; 13676.4,3148.2 13707.2,3179.1 ; 13707.23,3179.07 cw(c13714.3,3172) 13721.37,3164.93 ; 13716.76,3131.06 cw(c13731.4,3145.7) 13716.76,3160.34 ; 13716.8,3131.1 13743.6,3104.3 13936.2,3104.3 13960.9,3079.7 ; 13716.8,3160.4 13721.4,3164.9 ; 13971.5,3084.1 13971.5,3083.5 13978.1,3077
DSI-CKP: U1.110 U16.20 | length 869
  Inner2 w4.7: 13570.8,3409 13570.8,3396.4 13562.3,3388 13562.3,3383.3 13563,3382.6 13563,3300 13615.8,3247.2 ; 13613.9,3216 13615.8,3217.9 ; 13613.93,3215.97 ccw(c13621,3208.9) 13628.07,3201.83 ; 13615.84,3217.86 ccw(c13601.2,3232.5) 13615.84,3247.14 ; 13628,3201.8 13656.3,3230 ; 13654.63,3169.97 ccw(c13661.7,3162.9) 13668.77,3155.83 ; 13654.7,3169.9 13685.5,3200.8 ; 13656.26,3230.04 cw(c13670.9,3215.4) 13685.54,3200.76 ; 13668.8,3155.8 13699.7,3186.6 ; 13699.66,3186.64 cw(c13714.3,3172) 13728.94,3157.36 ; 13724.3,3138.7 13748,3115 13940.7,3115 13971.5,3084.1 ; 13724.3,3152.8 13728.9,3157.4 ; 13724.33,3138.63 cw(c13731.4,3145.7) 13724.33,3152.77 ; 13960.9,3079.7 13960.9,3069.9 13976.4,3054.3 v1(13976.4,3052)
  other v6: 13543.2,3409
DSI-D0N: U1.113 U16.26 | length 1026.7
  Top Layer w4.7: U1.113@13655.4,3620.7 13691.6,3620.7 13705.9,3606.4 13778,3606.4 13787.4,3615.8 v1(13801,3615.8) ; U16.26 13907.1,3154.1 13920.4,3167.4 v1@13928,3167.4
  Inner2 w4.7: v1(13801,3615.8) 13814.5,3615.8 13824,3606.4 13833.1,3606.4 13893,3546.5 13893,3461.8 cw(c13872.3,3461.8) 13872.3,3441.1 13872.2,3441.1 ccw(c13872.2,3431.1) 13872.2,3421.1 13912,3421.1 cw(c13912,3400.4) 13912,3379.7 13863.3,3379.7 ccw(c13863.3,3369.7) 13863.3,3359.7 13912,3359.7 cw(c13912,3339) 13912,3318.3 13863.3,3318.3 ccw(c13863.3,3308.3) 13863.3,3298.3 13872.3,3298.3 cw(c13872.3,3277.6) 13893,3277.6 13893,3241.4 13924.3,3210.1 13924.3,3172.4 v1(13928,3168.7)
DSI-D0P: U1.112 U16.24 | length 1006.8
  Top Layer w4.7: U1.112@13655.4,3581.3 13691.6,3581.3 13705.9,3595.7 13778,3595.7 13787.4,3586.3 v1(13801,3586.3) ; U16.24 v1(13930.8,3145)
  Inner2 w4.7: v1(13801,3586.3) 13814.5,3586.3 13824,3595.7 13828.7,3595.7 13882.3,3542 13882.3,3461.8 cw(c13872.3,3461.8) 13872.3,3451.8 13872.2,3451.8 ccw(c13872.2,3431.1) 13872.2,3410.4 13912,3410.4 cw(c13912,3400.4) 13912,3390.4 13863.3,3390.4 ccw(c13863.3,3369.7) 13863.3,3349 13912,3349 cw(c13912,3339) 13912,3329 13863.3,3329 ccw(c13863.3,3308.3) 13863.3,3287.6 13872.3,3287.6 cw(c13872.3,3277.6) 13882.3,3277.6 13882.3,3237 13910.8,3208.5 13910.8,3158.3 13924.1,3145 v1(13930.8,3145)
DSI-D1N: U1.116 U16.18 | length 1012.4
  Top Layer w4.7: 13655.4,3699.4 13691.6,3699.4 13705.9,3713.8 13773,3713.8 13782.4,3704.4 13796,3704.4 ; v1(13985.3,3183.7) 13986.6,3182.4 13986.6,3169.6 14008.1,3148.1 14008.1,3143.4 14001.6,3136.9 U16.18
  Inner2 w4.7: 13796,3704.4 13809.5,3704.4 13819,3713.8 13899.1,3713.8 13993,3619.9 13993,3572.3 cw(c13983,3572.3) 13983,3562.3 13973.3,3562.3 ccw(c13973.3,3541.6) 13973.3,3520.9 14017,3520.9 cw(c14017,3510.9) 14017,3500.9 14013.7,3500.9 ccw(c14013.7,3480.2) 13993,3480.2 13993,3204.9 13985.3,3197.2 v1(13985.3,3183.7)
  other v1: 13796,3733.9
DSI-D1P: U1.115 U16.16 | length 1023.7
  Top Layer w4.7: 13655.4,3738.8 13691.6,3738.8 13705.9,3724.5 13773,3724.5 13782.4,3733.9 13796,3733.9 ; v1(14011.4,3185.8) 14011.4,3159.8 14018.8,3152.5 14018.8,3143.4 14025.3,3136.9 U16.16
  Inner2 w4.7: 13796,3733.9 13809.5,3733.9 13819,3724.5 13903.5,3724.5 14003.7,3624.3 14003.7,3572.3 cw(c13983,3572.3) 13983,3551.6 13973.3,3551.6 ccw(c13973.3,3541.6) 13973.3,3531.6 14017,3531.6 cw(c14017,3510.9) 14017,3490.2 14013.7,3490.2 ccw(c14013.7,3480.2) 14003.7,3480.2 14003.7,3207.1 14011.4,3199.4 v1(14011.4,3185.8)
  other v1: 13796,3704.4
DSI-D2N: U1.118 U16.14 | length 1150.3
  Top Layer w4.7: U1.118@13655.4,3817.6 13691.6,3817.6 13705.9,3803.2 13715.1,3803.2 13715.2,3803.1 13767,3803.1 13776.5,3812.6 v1(13790,3812.6) ; U16.14 14048.9,3136.9 14055.3,3143.4 14055.3,3199.4 14053.1,3201.7 v1(14053.1,3215) ; 14072.5,3122.3 14072.5,3136.9 14066,3143.4 14066,3195 14079.3,3208.2 14079.3,3214.9
  Inner2 w4.7: v1(13790,3812.6) 13803.6,3812.6 13813,3803.1 13955,3803.1 14078.7,3679.4 14078.7,3215.5 14079.3,3214.9
DSI-D2P: U1.117 U16.12 | length 941.1
  Top Layer w4.7: U1.117@13655.4,3778.2 13691.6,3778.2 13705.9,3792.5 13710.6,3792.5 13710.7,3792.4 13767,3792.4 13776.5,3783 v1(13790,3783)
  Inner2 w4.7: v1(13790,3783) 13803.6,3783 13813,3792.4 13950.6,3792.4 14068,3675 14068,3250.6 14053.1,3235.7 14053.1,3215
  other v1: 14079.3,3214.9
DSI-D3N: U1.121 U16.30 | length 1058.2
  Top Layer w4.7: U1.121@13655.4,3935.7 13726.6,3935.7 13740.9,3921.3 13763,3921.3 13772.4,3930.7 v1(13786,3930.7) ; v1(13825.8,3175.3) 13835.4,3165.7 13848.7,3165.7 13866.4,3148.1 13866.4,3143.4 13859.9,3136.9 U16.30
  Inner2 w4.7: v1(13786,3930.7) 13772.4,3930.7 13763,3921.3 13753.9,3921.3 13723,3890.5 13723,3336.4 13816.2,3243.2 13816.2,3184.9 v1(13825.8,3175.3)
DSI-D3P: U1.120 U16.28 | length 1032.5
  Top Layer w4.7: U1.120@13655.4,3896.3 13726.6,3896.3 13740.9,3910.6 13763,3910.6 13772.4,3901.2 v1(13786,3901.2) ; v1(13846.7,3196.2) 13856.3,3186.6 13856.3,3173.3 13877.1,3152.5 13877.1,3143.4 13883.5,3136.9 U16.28
  Inner2 w4.7: v1(13786,3901.2) 13772.4,3901.2 13763,3910.6 13758.3,3910.6 13733.7,3886 13733.7,3340.9 13837.1,3237.4 13837.1,3205.8 v1(13846.7,3196.2)
E7/PG17/UART0_TX/3V3: U1.33 U6.6 | length 409.1
  Top Layer w11: U1.33 12316.8,5148.8 12358,5190 12508,5190 12526.1,5208.1 U6.6
E13/HPOUTFB: U1.9
E15/MICIN2P: U1.141
E16/MBIAS: U1.8
E19/TVOUT0: U1.135
F13/HPOUTL: U1.15
GND: C1.2 C2.2 C3.1 C4.2 C5.1 C6.1 C8.1 C9.1 C10.1 C13.2 C14.2 C15.2 C16.1 C17.2 C20.1 C24.1 C25.1 C26.1 C27.1 C28.1 C29.1 C30.1 C34.1 C38.1 C39.2 C40.1 C41.1 C42.1 C43.1 Q1.2 Q2.2 Q5.2 R2.1 R4.1 R5.1 R6.2 R14.2 R19.2 R23.1 R32.1 SCREW1.1 SCREW2.1 SCREW3.1 SCREW4.1 SW8.0 U1.5 U1.16 U1.18 U1.20 U1.25 U1.28 U1.31 U1.51 U1.59 U1.66 U1.76 U1.84 U1.88 U1.89 U1.92 U1.104 U1.109 U1.114 U1.119 U1.124 U1.129 U1.134 U1.136 U1.143 U1.148 U2.3 U2.9 U5.2 U6.2 U9.14 U9.17 U11.7 U12.1 U12.6 U14.11 U15.2 U16.5 U16.8 U16.10 U16.11 U16.13 U16.15 U16.17 U16.19 U16.21 U16.23 U16.25 U16.27 U16.29 U16.31 U16.32 U16.39 U16.40 U16.41 U21.5 U21.9 U22.3 U22.7 USB1.A1 USB1.A12 USB1.B1 USB1.B12 | length 95.7
  Top Layer w8: C3.1 11525.7,6207.2 U11.7
  other v3: 12028,3182.1 12028,3210 12028,3240 12028,3270
  other v4: 13960.3,3169.6 13801.1,3174 13883.9,3200 13953,3200 14033,3200 14103,3200 13863,3215 13768,3570 13768,3635 13818,3685 13818,3755 13763,3765 13763,3830 13763,3885 13763,3947
  other v5: 11583.3,3375.3 11622.7,3375.3 11583.3,3414.7 11622.7,3414.7
  other v7: 12628,3239.3 12628,3265
h0wB!g!$!t: 
HBIAS: U1.7
HP_DET: U1.13
HPOUTR: U1.14
J2/REFCLK_OUT/1V8: U1.60
K17/PB6/UART3_TX/3V3: U1.98
LDO1: U8.15
LDO2: U8.17
LED_ALM: U1.46 U3.5 | length 808
  Top Layer w5.9: U3.5 11599.8,4838.2 11754.3,4683.7 U1.46@12080.6,4683.7
LINEOUTLN: R16.1 U1.145 | length 265.8
  Top Layer w8: U1.145 13712.4,4890.6 13748,4855 13748,4775 13778,4745 13810.5,4745 R16.1
LINEOUTLP: R15.1 U1.144 | length 299
  Top Layer w8: U1.144 13686.8,4851.2 13718,4820 13718,4705 13748,4675 13810.5,4675 R15.1
LRADC: U1.12
M6/PE17/D_JTAG_CK/IR-TX: U1.61
M_EN: R6.1 U1.93 U9.1
M_FAULT: R7.2 U9.8
MAIN_PG: R3.2 U2.7 | length 143.4
  Top Layer w5.9: U2.7 11955.8,5307.8 11963,5315 11963,5382.5 R3.2
N1/PE11/LVDS_LCD_EN/LCD_HDMI_MIPI_RST/NCSI0_D7/3V3: U1.72
N3/NMI/1V8: U1.63
N4/PE14/D_JTAG_MS/RGMII-RXD3: U1.82
N6/PE16/D_JTAG_DO/PWM7: U1.62
NET9: Q2.1 R4.2
NET10: Q1.1 R5.2
P2/PE9/RMII-MDIO: U1.68
P3/PE10/PWM4/BL_PWM/RMII-EPHY-25M/NCSI0_D6/3V3: U1.67
PA10: R20.2
PD19/LVDS1-V3N: U1.133
PD_ALM: U1.45 U3.6 | length 799.8
  Top Layer w5.9: U3.6 11660.2,4857.8 11794.9,4723.1 U1.45@12080.6,4723.1
PG0/RGMII-RXCTRL: U1.49
PG1: U8.16
PG1/RGMII--RXD0: U1.48
PG2: U8.18
PG14/RGMII-MDC: U1.36
PG15/RGMII-MDIO: U1.37
PWM5: U1.83
R1/PE6/UART5_TX/NCSI0_D2/3V3: U1.71
R3/PE8/RMII-MDC: U1.69
RES: Q5.1 U16.3 | length 170.9
  Top Layer w9: Q5.1 14105,3295 14153,3295 14178.8,3269.2 U16.3
RL_LCD: U16.33 U22.5
ROW1: U1.108
ROW2: U1.107
RX1: U1.44 U4.13 | length 2696.1
  Top Layer w8: U1.44 12810.4,4772.4 12988,4950 v1(13208,4950) ; v1(13593,6080) 13661.4,6080 U4.13
  Bottom Layer w8: v1(13208,4950) 13428,4950 13528,5050 13528,6015 v1(13593,6080)
SCL: U1.70 | length 82.4
  Top Layer w5.9: U1.70@12080.6,3738.8 v1(12163,3738.8)
SDA: U1.73 | length 82.4
  Top Layer w5.9: U1.73@12080.6,3620.7 v1(12163,3620.7)
SOL_EN: C30.2 R27.1 U5.4 | length 116.1
  Top Layer w8: U5.4 v3(12408,5715.1) ; v3@12548,5715 12548.1,5715.1 v3@12553,5715.1 ; 12553,5680.3 v3@12553,5715.1 ; 12553,5749.5 v3@12553,5715.1 ; v3(12558,5715.1) v3@12553,5715.1
SOM_USB0_D_N: U1.26 USB1.A7 USB1.B7
SOM_USB0_D_P: U1.27 USB1.A6 USB1.B6
SOM_USB1_D_N: U1.29
SOM_USB1_D_P: U1.30
SPI1_CLK: U1.103 U8.22 | length 2556.1
  Top Layer w5.9: U8.22 v1(11488,4327.8) ; U1.103@13261.7,3502.6 v1(13261.7,3780)
  Bottom Layer w5.9: v1(11488,4327.8) 12930.2,4327.8 13261.7,3996.3 v1(13261.7,3780)
SPI1_CS: U1.106 U8.28 | length 2771.1
  Top Layer w5.9: U8.28 v1(11488,4445.9) ; v1(13378,3780) 13378,3504.4 U1.106@13379.8,3502.6
  Bottom Layer w5.9: v1(11488,4445.9) 13012.1,4445.9 13378,4080 v1(13378,3780)
SPI1_DRDY: U1.99 U8.26 | length 2477.5
  Top Layer w5.9: U8.26 v1(11428,4406.5) ; U1.99@13104.2,3502.6 v1(13104.2,3785)
  Bottom Layer w5.9: v1(11428,4406.5) 11428,4300 11483,4245 12828,4245 13104.2,3968.8 v1(13104.2,3785)
SPI1_HOLD: U1.102
SPI1_MISO: U1.101 U8.20 | length 2454.3
  Top Layer w5.9: U8.20 11486.4,4288.4 v1(11488,4290) ; U1.101@13183,3502.6 13183,3781.6 v1(13184.7,3783.3)
  Bottom Layer w5.9: v1(11488,4290) 12873,4290 13184.7,3978.3 v1(13184.7,3783.3)
SPI1_MOSI: U1.105 U8.24 | length 2649
  Top Layer w5.9: U8.24 11485.8,4367.2 v1(11488,4365) ; U1.105@13340.4,3502.6 v1(13340.4,3780)
  Bottom Layer w5.9: v1(11488,4365) 12968,4365 13340.4,3992.6 v1(13340.4,3780)
SPI1_WP: U1.100
T2/PE4/UART4_TX/NCSI0_D0/3V3: U1.74
T133_RESET: C29.2 R26.1 U1.64 U6.3 | length 252.2
  Top Layer w11: C29.2 11910.5,4073 R26.1 11925.4,3985 U1.64
TX1: U1.43 U4.14 | length 2680.8
  Top Layer w8: U1.43 12764.8,4811.8 12943,4990 v1(13198,4990) ; v1(13598,6145) U4.14
  Bottom Layer w8: v1(13198,4990) 13368,4990 13448,5070 13448,5995 v1(13598,6145)
U1/PE1/RGMII-RXD0/RMII-RXD0: U1.78
U2/PE2/RGMII-RXD1/RMII-RXD1: U1.79
U3/PE3/RGMII-TXCK/RMII-TXCK: U1.77
V1/PE0/RGMII-RXCTRL/RMII-CRS-DV: U1.80
VBUS: U3.18 U3.19 USB1.A4 USB1.A9 USB1.B4 USB1.B9
VDD: C6.2 C20.2 C26.2 R1.2 R3.1 R7.1 R8.2 R9.2 R26.2 U2.4 U2.5 U6.1 U14.6 U15.1 U15.3 | length 343.7
  Top Layer w9: C26.2 13964.9,3509.5 U15.3 13985.6,3502.6 14004,3521 14004,3564 13990.6,3577.4 U15.1 ; C20.2@13925.5,3984 13925.5,3977.5 13963,3940 13992.9,3940 U14.6
  other v3: 11901.1,5105 11933.6,5105 11901.5,5134.2 11934,5134.2
VDDI: C27.2 Q3.2 R21.2 U15.5 | length 267.2
  Top Layer w9: U15.5@14078.9,3579.9 14084.4,3574.4 C27.2 14156.1,3574.4 R21.2 14218.3,3512.2 Q3.2
VIN: C38.2 SW8.2 U3.21 U3.22 U21.1 U21.2 U21.4
VLED+: C43.2 D4.2 U16.34 U16.35 | length 629.3
  Top Layer w9: C43.2@13418,3375.5 13752.5,3375.5 13800.8,3327.2 U16.35 13800.8,3202.8 13787.2,3189.2 13787.2,3188.7 13780.8,3182.4 13780.8,3165.5 13812.7,3133.7 U16.34
VLED-: R32.2 U16.37 U16.38 U22.1 | length 504.8
  Top Layer w9: U22.1 13465.2,3195.3 R32.2 13615.5,3177.5 13670.7,3122.3 U16.38 13765.4,3197.4 13777.2,3209.2 U16.37
VSN: C24.2 U14.2 U16.2 | length 238.5
  Top Layer w9: U14.2 14158.9,3844.1 14188.5,3814.5 C24.2 ; U16.2 14193,3124.7 v2(14193,3155)
VSP: C25.2 Q4.3 U14.9 | length 603.8
  Top Layer w9: Q4.3 13858,3405.3 13858,3630 13898,3670 C25.2 13998,3700.5 13998,3830 14012.1,3844.1 U14.9
pads on no net: CN1.3 CN1.4 CN2.5 CN2.6 CN4.5 CN4.6 CN6.2 CN6.7 CN6.8 R18.2 SW8.1 U3.30 U3.31 U4.3 U4.4 U4.5 U4.6 U4.7 U4.9 U4.10 U4.15 U4.16 U4.17 U4.18 U5.6 U6.7 U6.8 U8.1 U8.2 U8.3 U8.4 U8.5 U8.6 U8.7 U8.8 U8.9 U8.10 U8.30 U8.31 U9.3 U9.6 U9.13 U15.4 U16.1 U16.7 U16.9 U16.36 USB1.1 USB1.2 USB1.3 USB1.4 USB1.A5 USB1.A8 USB1.B5 USB1.B8

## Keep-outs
Board Outline Layer:
  the board outline again, w10

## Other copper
Top Layer:
  region net $25N148: 11188,3605 11188,3625 11198,3635 11403,3635 11453,3585 11453,3480 11468,3465 11513,3465 11518,3460 11518,3455 11513,3450 11463,3450 11438,3475 11438,3555 11398,3595 11198,3595
  region net $25N149: 11188,3555 11197.6,3564.6 11388.4,3564.6 11430.3,3522.7 11430.3,3442.7 11458,3415 11501,3415 11508.8,3407.3 11503,3401.5 11503,3400 11453,3400 11419.2,3433.8 11419.2,3503.8 11408,3515 11198,3515 11188,3525
  region net $25N150: 11188,3475 11194.7,3481.7 11396.3,3481.7 11413,3465 11413,3425 11448,3390 11496.1,3390 11508.8,3377.4 11490.4,3377.4 11488,3375 11443,3375 11398,3420 11398,3440 11393.6,3444.4 11193.6,3444.4 11188,3450
  region net $25N151: 11195.2,3402.2 11390.8,3402.2 11403,3390 11403,3365 11428,3340 11507.8,3340 11516.8,3331 11516.8,3328.8 11513,3325 11413,3325 11378,3360 11198,3360 11187.1,3370.9 11187.1,3394.1
  region net +VPS: 12351.5,5766.5 12429.5,5766.5 12438,5775 12438,5825 12428,5835 12353,5835 12343,5845 12343,5930 12348,5935 12393,5935 12398,5930 12398,5870 12408,5860 12488,5860 12528,5820 12528,5730 12523,5725 12441.5,5725 12429.5,5737.8 12351.5,5737.5 12343,5743.5 12343,5759.9
  region net 12V: 11188,5620 11203.8,5635.7 11402.3,5635.7 11453,5585 11548,5585 11583,5550 11861.8,5550 11916.4,5604.6 11967.4,5604.6 11967.4,5494.4 11963,5490 11908,5490 11879.3,5518.7 11469.3,5518.7 11402.9,5585.1 11202.4,5585.1 11188,5599.5
  region net 12V: 11188,5760 11188,5785 11194.8,5791.8 11429.8,5791.8 11448.6,5810.6 11511.4,5810.6 11525.8,5796.2 11763,5796.2 11793,5766.2 11793,5577.2 11820.2,5550 11743,5550 11773,5580 11773,5760 11763,5770 11538,5770 11533,5765 11423,5765 11407.7,5749.7 11198.3,5749.7
  region net 12V: 11916.4,5592.2 11928.7,5604.6 12008.4,5604.6 12028,5585 12248,5585 12303,5640 12373,5640 12383,5630 12363,5610 12363,5568.5 12276.5,5568.5 12248,5540 12063,5540 12013,5490 11935.5,5490 11916.4,5509.1
  region net VDD: 11923.2,5264.5 11948.5,5264.5 11953,5260 11953,5155 11948,5150 11887.5,5150 11882.5,5155 11882.5,5209.5 11923.2,5250.2
  region net VDD: 11882.5,5125 11953,5125 11953,5100 11938,5085 11898,5085 11882.5,5100.5
  region net VIN: 11513.9,5230 11446.7,5230 11435.8,5217.5 11436.1,5171.2 11408,5147 11314.3,5146.9 11313,5151.8 11314.3,5153.1 11314.3,5180 11398,5180 11408,5190 11408,5245 11463,5300 11513,5300 11513,5295.8 11513.9,5294.9 11513.9,5270.3 11472.9,5271 11465.1,5262.5 11465.1,5247.9 11472.3,5240.7 11513.9,5240.7
  region net VDD: 11882.5,5182.2 11953,5182.2 11953,5125 11948,5120 11882.5,5120
  region net $25N181: 12579.1,3217 12579.1,3311.1 12644.6,3376.6 12783,3376.6 12783,3305 12773,3295 12598,3295 12586.9,3283.9 12586.9,3217
  region net 5V: 12554.5,3228.9 12554.5,3288.5 12543,3300 12523,3300 12508,3315 12508,3435 12513,3435 12538,3460 12538,3545 12548,3555 12603,3555 12608,3550 12608,3365 12568.2,3325.2 12568.2,3228.9
  region net +VPS: 12663,3100 12660.9,3102.1 12660.9,3186.8 12704.1,3230 12798.7,3230 12809.7,3219 12809.7,3178.3 12828,3160 12828,3095 12823,3090 12723,3090 12713,3100
  region net 5V: 11871.8,3376.2 11690.2,3376.2 11690.2,3390 11743,3390 11776.1,3423.1 11871.3,3423.1 11903.2,3455 12063,3455 12073,3445 12073,3355 12059.8,3341.8 11906.2,3341.8
  region net VLED+: 13293,3325 13288,3330 13288,3390 13293,3395 13428,3395 13433,3390 13433,3360 13427.2,3354.2 13382.2,3354.2 13353,3325
  region net $25N352: 13168,3390 13228,3390 13233,3385 13233,3320 13268,3285 13268,3245 13183,3245 13178,3250 13178,3300 13163,3315 13163,3385
  region net 5V: 13363,3090 13203,3090 13155.7,3137.3 13155.7,3195 13174.9,3214.3 13288.7,3214.3 13298,3205 13343,3205 13348.6,3199.4 13348.6,3164.4 13368,3145 13368,3095
  region net +VPS: 11569,5299.8 11569.2,5300 11603,5300 11623,5320 11623,5360 11643,5380 11793,5380 11818,5355 11818,5330 11833,5315 11858,5315 11858,5300 11753,5300 11723,5270 11568,5270 11568,5300 11568.8,5300

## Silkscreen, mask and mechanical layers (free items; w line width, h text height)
Top Silkscreen Layer:
  text "编号：JLC04161H-3313（成品板厚 1.56mm ±10%） / 成品板厚：1.6mm / 外层铜厚：1 oz / 内层铜厚：0.5 oz /  / +------+---------------------------+----------+-----------+ / | 层名 | 材料                      | 厚度(mil) | 厚度(mm)  | / +------+---------------------------+----------+-----------+ / | L1   | 外层铜厚 1oz              | 1.38     | 0.0350    | / |      | PP 3313 RC57% 4.2mil      | 3.91     | 0.0994    | / +------+---------------------------+----------+-----------+ / | L2   | 内层铜厚                  | 0.60     | 0.0152    | / +------+---------------------------+----------+-----------+ / |      | 芯板 1.3mm H/HOZ 含铜      | 49.80    | 1.2650    | / +------+---------------------------+----------+-----------+ / | L3   | 内层铜厚                  | 0.60     | 0.0152    | / +------+---------------------------+----------+-----------+ / |      | PP 3313 RC57% 4.2mil      | 3.91     | 0.0994    | / +------+---------------------------+----------+-----------+ / | L4   | 外层铜厚 1oz              | 1.38     | 0.0350    | / +------+---------------------------+----------+-----------+" at 11978,7590 h120
Document Layer:
  lines w10 net h0wB!g!$!t: 3005,9654 3320,9654

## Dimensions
10943,2993.1 to 10943,3268.7 on Document Layer
10943,3737.5 to 10943,3796.6 on Document Layer
10523,3973.3 to 10523,2996.9 on Document Layer
10888,6654.5 to 10888,6378.9 on Document Layer
10828,6064.3 to 10828,5965.9 on Document Layer
10938,5430.5 to 10938,5489.5 on Document Layer
10423,5426.7 to 10423,6654.5 on Document Layer
10658,3798.1 to 10658,2993.1 on Document Layer
14283,2760 to 12987.7,2760 on Document Layer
